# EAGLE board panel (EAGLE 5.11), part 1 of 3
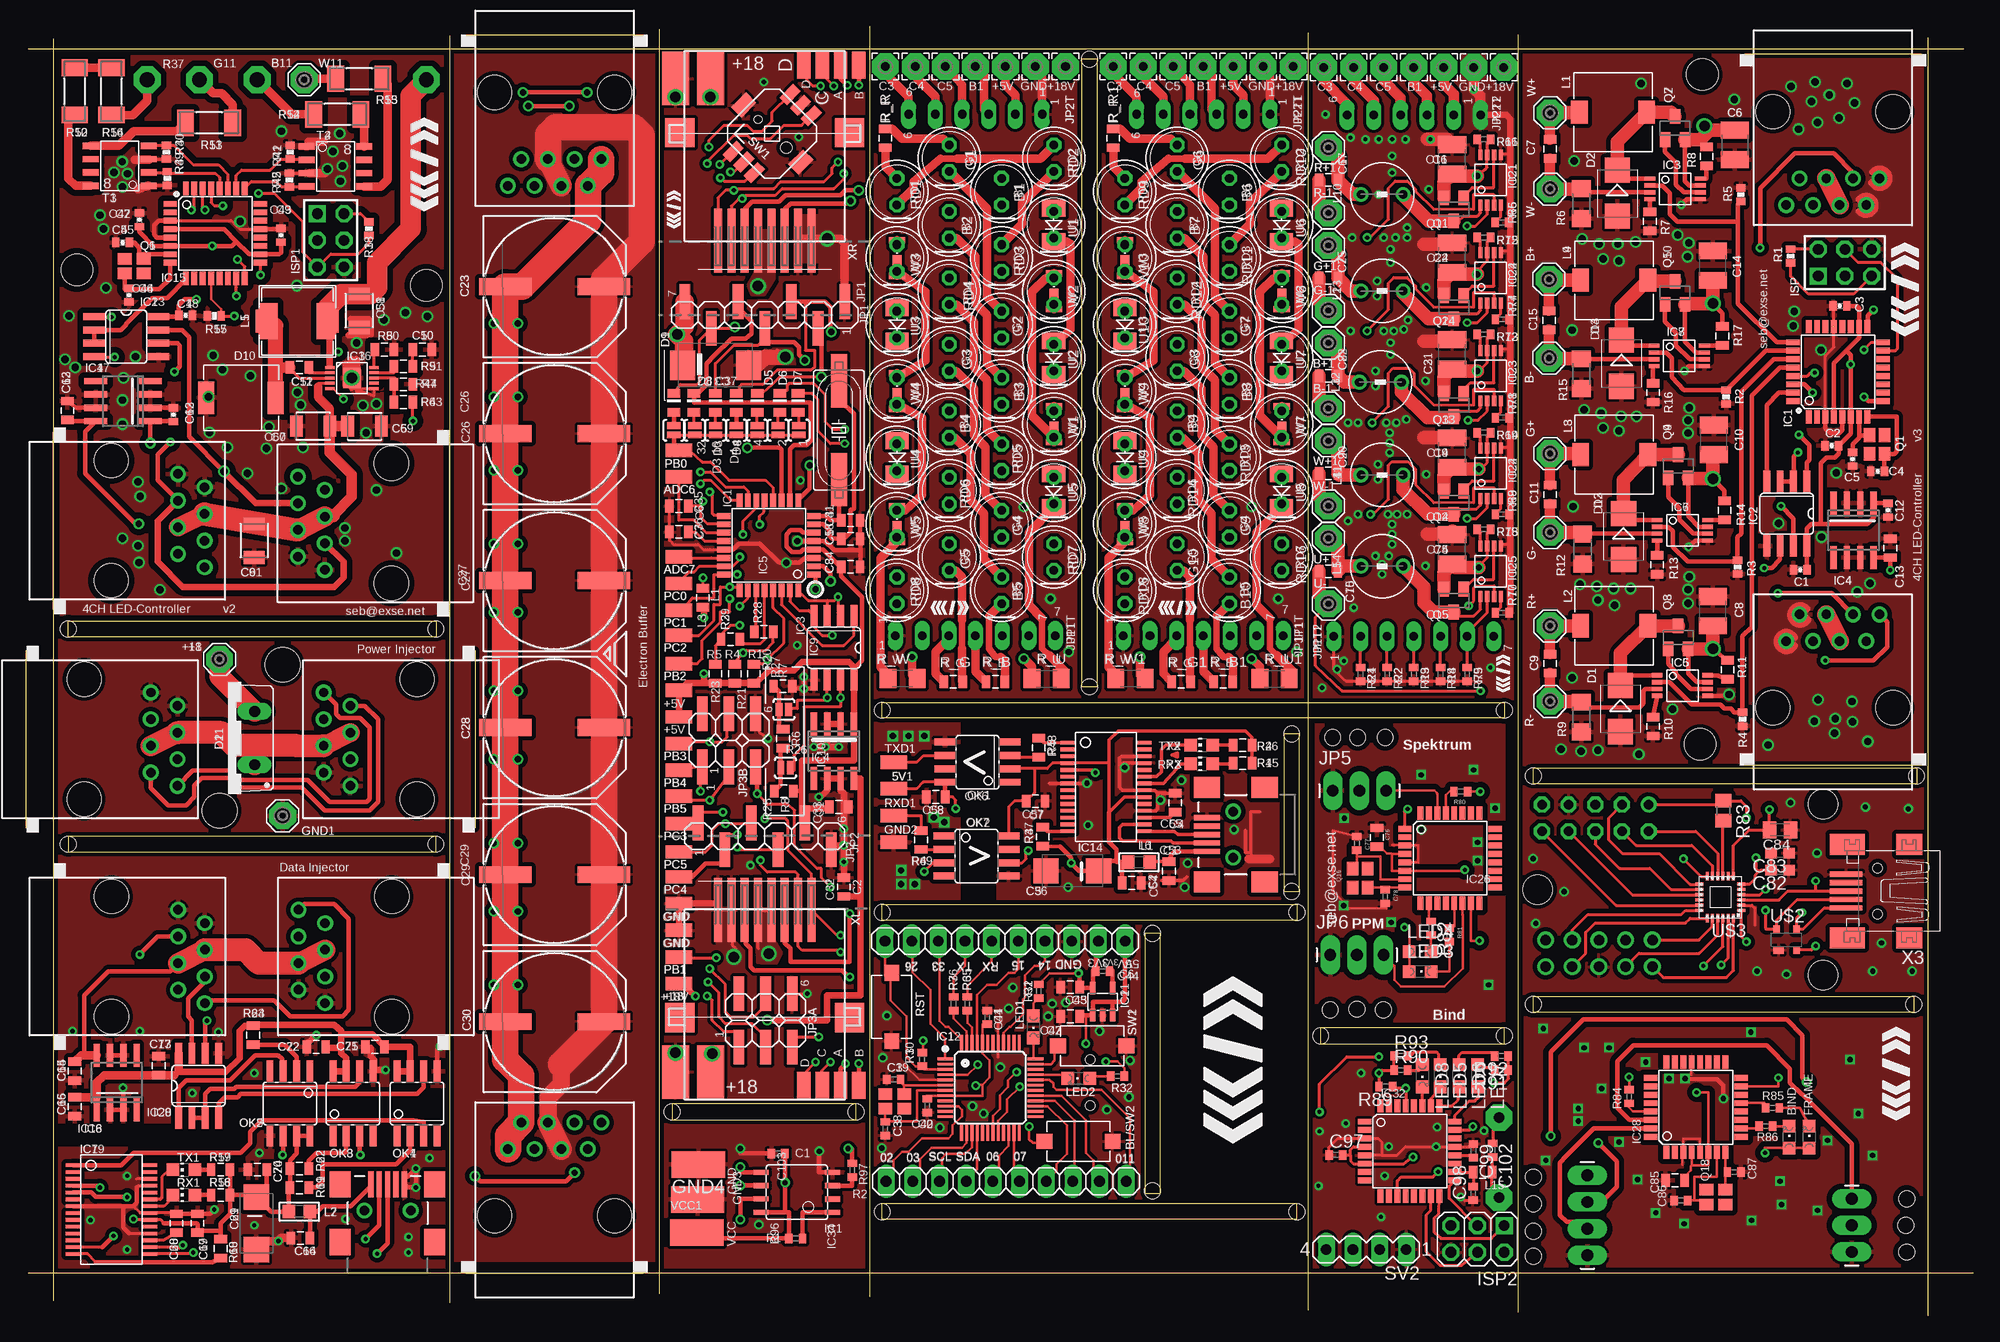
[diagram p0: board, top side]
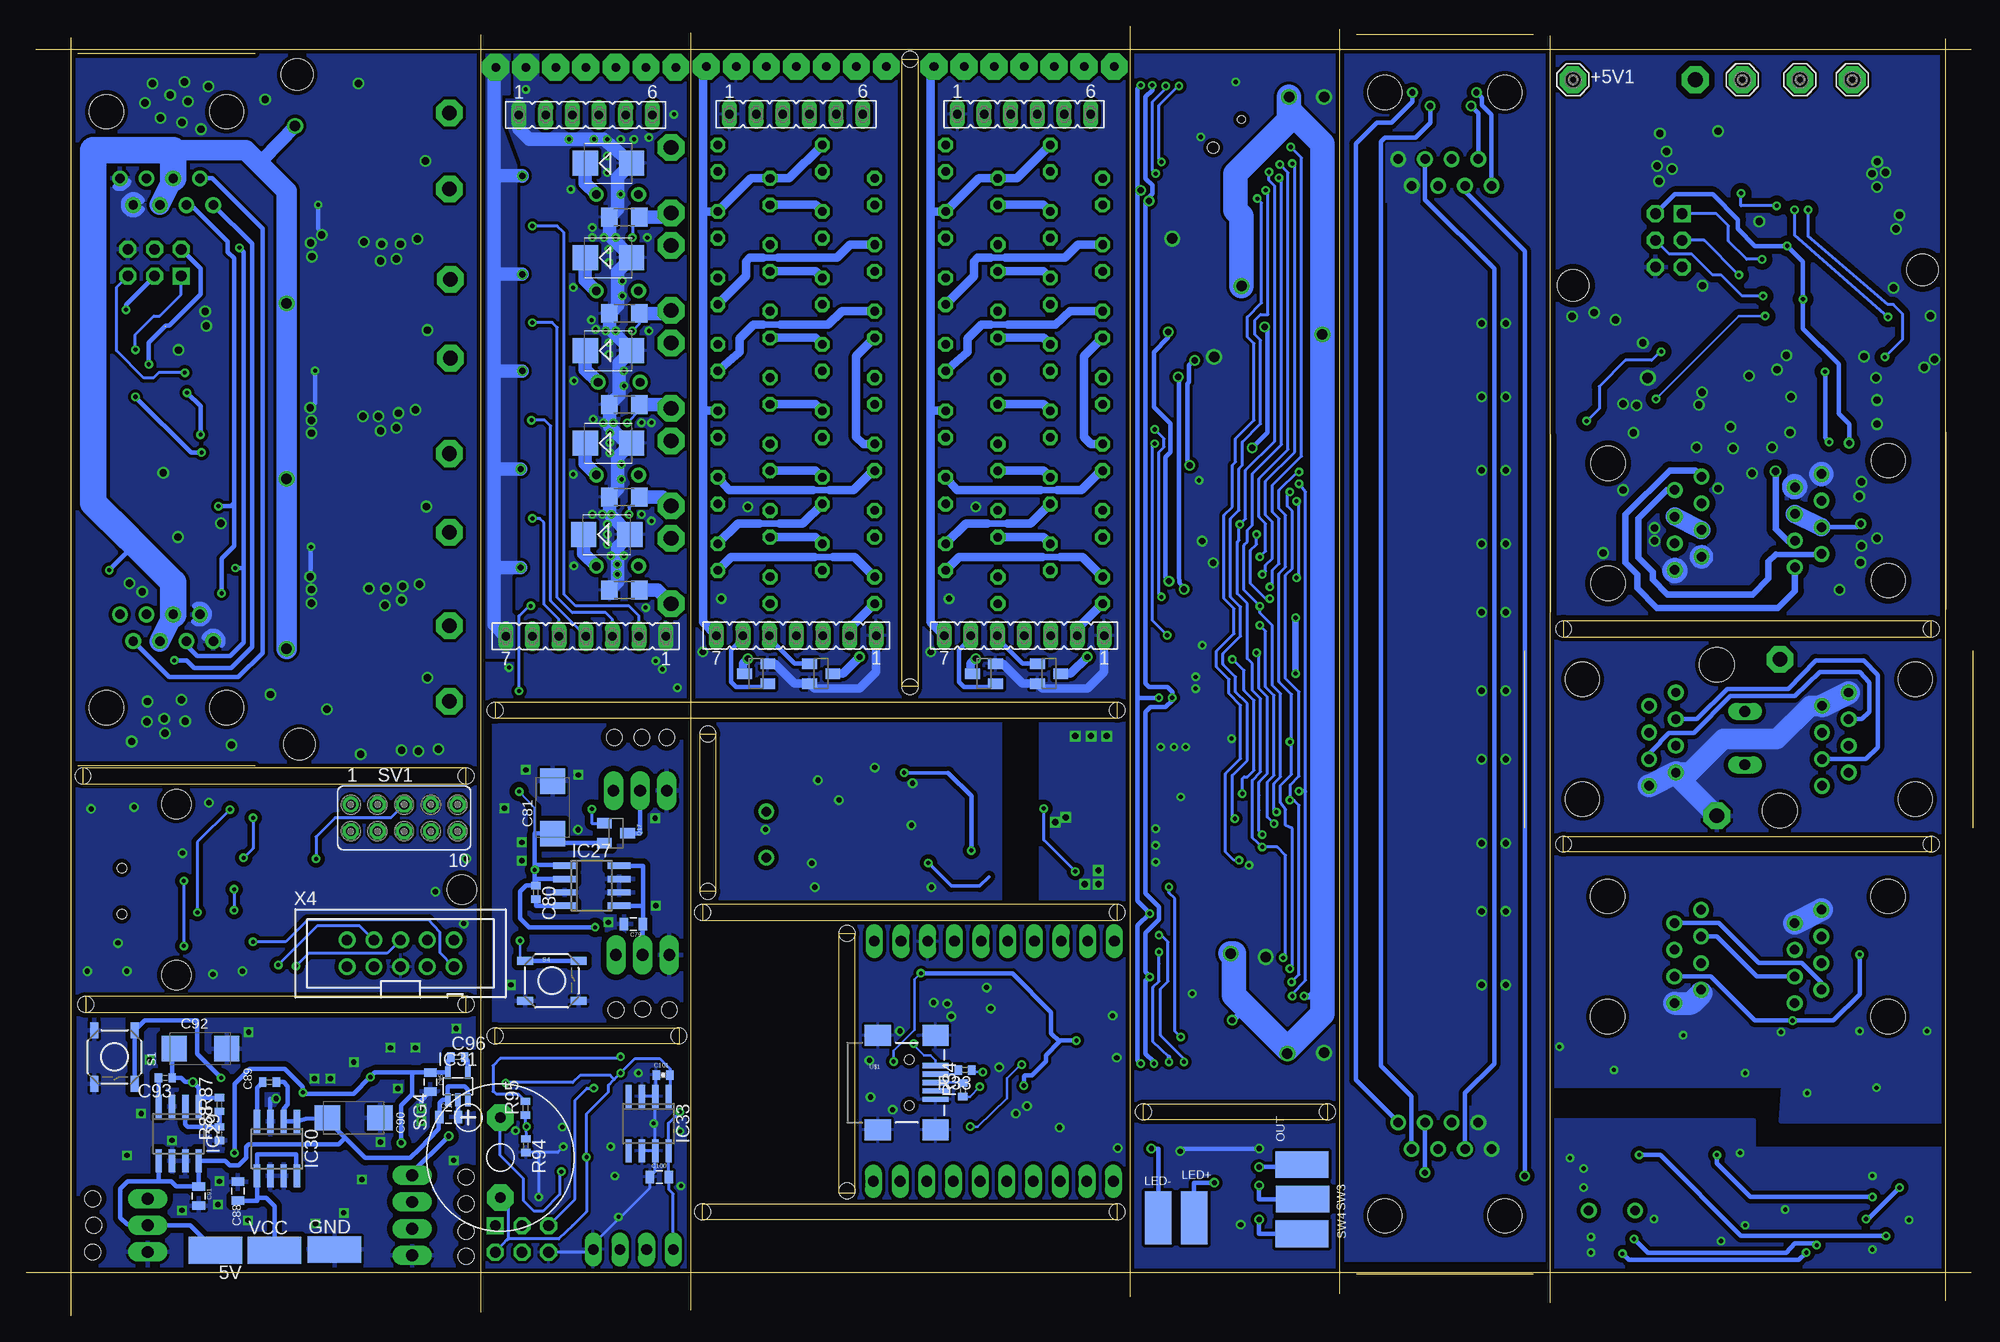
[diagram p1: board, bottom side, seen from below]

Size 185.41 x 122.8 mm. Coordinates in mm from the lower left corner, seen from the top.
Outline: 57 segments
Copper layers (1*16): Top 0.035mm / dielectric 1.5mm / Bottom 0.035mm
Design rules "default *": minimum track width 0.2mm, minimum drill 0.4mm, track to track 0.2mm, track to pad 0.2mm, pad to pad 0.2mm, via to via 0.2mm, smd to smd 0mil, copper to edge 0.4mm, drill to drill 8mil, minimum pad ring 0.3mm, minimum via ring 8mil, stop-mask expansion 4mil, vias tented up to drill 40mil, thermal gap 10mil
Holes 3.3 mm at 18.41,48.1 24.41,62
Holes 3 mm at 38.11,98.1 4.81,99.6 159.41,54.4 159.61,118.2
Holes 1.5 mm at 124.17,29.12 126.72,29.2 129.25,29.12 124.41,55.07 126.79,55.07 129.41,55.07 179.07,6.06 179,8.6 179.07,11.14 143.51,5.66 143.51,8.04 143.51,10.66 143.51,13.2 4.01,65.4 39.01,65.4 4.01,44.9 39.01,44.9 61.51,19.4 79.01,19.4 81.51,9.9 121.01,9.9 81.51,38.4 121.01,38.4 120.51,40.4 120.51,55.4 143.51,51.4 180.01,51.4 107.26,11.9 107.26,36.4 81.51,57.65 140.76,57.65 101.26,59.9 101.26,119.65 123.26,26.65 140.76,26.65 143.51,29.65 179.76,29.65
Holes 2.8 mm at 171.13,48.72 171.13,32.45 143.93,40.59
tRestrict: 2 lines

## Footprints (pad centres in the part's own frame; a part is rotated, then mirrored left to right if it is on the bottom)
SMD2,54-5,08 = smd 2.54 x 5.08: 1 0,0
SMD1,27-2,54 = smd 1.27 x 2.54: 1 0,0
SE14 = drill 1.397 pad 2.54 octagon: MP 0,0
LED5MM = drill 0.813 octagon: A -1.27,0; K 1.27,0
CHIPLED_0805 = smd 1.2 x 1.2: A 0,-1.05; C 0,1.05
SWITCH_MCTAEF = smd 1.5 x 1.4: 1 -3.25,0; 2 3.25,0
0402-CAP = smd 0.7 x 0.9: 1 -0.65,0; 2 0.65,0
C1210 = smd 1.6 x 2.7: 1 -1.4,0; 2 1.4,0
0805 = smd 0.8 x 1.2: 1 -0.9,0; 2 0.9,0
PANASONIC_H13 = smd 5 x 1.6: + 4.7,0; - -4.7,0
SMC_D = smd 2.4 x 2.8: + -3.15,0; - 3.15,0
C0402 = smd 0.7 x 0.9: 1 -0.65,0; 2 0.65,0
1210 = smd 1.2 x 2: 1 -1.6,0; 2 1.6,0
SMC_C = smd 2.4 x 2.4: + -2.5,0; - 2.5,0
C0603 = smd 1.1 x 1: 1 -0.85,0; 2 0.85,0
C0805K = smd 1.3 x 1.6: 1 -1,0; 2 1,0
SMB = smd 2.4 x 2.4: A 2.2,0; C -2.2,0
DIODE_0805 = smd 0.8 x 1.2: 1 -0.9,0; 2 0.9,0
DO214AB = smd 1.52 x 3.07: A 3.305,0; K -3.305,0
TO220ACS = drill 1.016 long: A 2.54,-2.54; C -2.54,-2.54
TQFP32-08 = smd 1.27 x 0.559: 1 -4.293,2.8; 2 -4.293,2; 3 -4.293,1.2; 4 -4.293,0.4; 5 -4.293,-0.4; 6 -4.293,-1.2; 7 -4.293,-2; 8 -4.293,-2.8; 17 4.293,-2.8; 18 4.293,-2; 19 4.293,-1.2; 20 4.293,-0.4; 21 4.293,0.4; 22 4.293,1.2; 23 4.293,2; 24 4.293,2.8 | smd 0.559 x 1.27: 9 -2.8,-4.293; 10 -2,-4.293; 11 -1.2,-4.293; 12 -0.4,-4.293; 13 0.4,-4.293; 14 1.2,-4.293; 15 2,-4.293; 16 2.8,-4.293; 25 2.8,4.293; 26 2,4.293; 27 1.2,4.293; 28 0.4,4.293; 29 -0.4,4.293; 30 -1.2,4.293; 31 -2,4.293; 32 -2.8,4.293
SO08 = smd 0.66 x 2.032: 1 -1.905,-3.073; 2 -0.635,-3.073; 3 0.635,-3.073; 4 1.905,-3.073; 5 1.905,3.073; 6 0.635,3.073; 7 -0.635,3.073; 8 -1.905,3.073
MSOP8 = smd 0.41 x 1.02: 1 -0.975,-2.4; 2 -0.325,-2.4; 3 0.325,-2.4; 4 0.975,-2.4; 5 0.975,2.4; 6 0.325,2.4; 7 -0.325,2.4; 8 -0.975,2.4
SO08' = smd 0.6 x 2.2: 1 -1.905,-2.6; 2 -0.635,-2.6; 3 0.635,-2.6; 4 1.905,-2.6; 5 1.905,2.6; 6 0.635,2.6; 7 -0.635,2.6; 8 -1.905,2.6
SOT23-5L = smd 0.55 x 1.2: 1 -0.95,-1.3; 2 0,-1.3; 3 0.95,-1.3; 4 0.95,1.3; 5 -0.95,1.3
LQFP48 = smd 1.5 x 0.25: 1 -4.3,2.75; 2 -4.3,2.25; 3 -4.3,1.75; 4 -4.3,1.25; 5 -4.3,0.75; 6 -4.3,0.25; 7 -4.3,-0.25; 8 -4.3,-0.75; 9 -4.3,-1.25; 10 -4.3,-1.75; 11 -4.3,-2.25; 12 -4.3,-2.75; 25 4.3,-2.75; 26 4.3,-2.25; 27 4.3,-1.75; 28 4.3,-1.25; 29 4.3,-0.75; 30 4.3,-0.25; 31 4.3,0.25; 32 4.3,0.75; 33 4.3,1.25; 34 4.3,1.75; 35 4.3,2.25; 36 4.3,2.75 | smd 0.25 x 1.5: 13 -2.75,-4.3; 14 -2.25,-4.3; 15 -1.75,-4.3; 16 -1.25,-4.3; 17 -0.75,-4.3; 18 -0.25,-4.3; 19 0.25,-4.3; 20 0.75,-4.3; 21 1.25,-4.3; 22 1.75,-4.3; 23 2.25,-4.3; 24 2.75,-4.3; 37 2.75,4.3; 38 2.25,4.3; 39 1.75,4.3; 40 1.25,4.3; 41 0.75,4.3; 42 0.25,4.3; 43 -0.25,4.3; 44 -0.75,4.3; 45 -1.25,4.3; 46 -1.75,4.3; 47 -2.25,4.3; 48 -2.75,4.3
SSOP28DB = smd 0.348 x 1.397: 1 -4.225,-3.656; 2 -3.575,-3.656; 3 -2.925,-3.656; 4 -2.275,-3.656; 5 -1.625,-3.656; 6 -0.975,-3.656; 7 -0.325,-3.656; 8 0.325,-3.656; 9 0.975,-3.656; 10 1.625,-3.656; 11 2.275,-3.656; 12 2.925,-3.656; 13 3.575,-3.656; 14 4.225,-3.656; 15 4.225,3.656; 16 3.575,3.656; 17 2.925,3.656; 18 2.275,3.656; 19 1.625,3.656; 20 0.975,3.656; 21 0.325,3.656; 22 -0.325,3.656; 23 -0.975,3.656; 24 -1.625,3.656; 25 -2.275,3.656; 26 -2.925,3.656; 27 -3.575,3.656; 28 -4.225,3.656
MSOP10-PAD = smd 0.305 x 0.889: 1 -1,-2.095; 2 -0.5,-2.095; 3 0,-2.095; 4 0.5,-2.095; 5 1,-2.095; 6 1,2.095; 7 0.5,2.095; 8 0,2.095; 9 -0.5,2.095; 10 -1,2.095 | smd 1.88 x 1.68: PAD 0,0
SOIC8 = smd 0.6 x 2.2: 1 -1.905,-2.6; 2 -0.635,-2.6; 3 0.635,-2.6; 4 1.905,-2.6; 5 1.905,2.6; 6 0.635,2.6; 7 -0.635,2.6; 8 -1.905,2.6
8S2 = smd 0.5 x 1.4: 1 -1.905,-3.404; 2 -0.645,-3.404; 3 0.625,-3.404; 4 1.895,-3.404; 5 1.905,3.404; 6 0.635,3.404; 7 -0.635,3.404; 8 -1.905,3.404
AVR-ISP-6 = drill 1.016 square: 1 -2.54,-1.27 | drill 1.016 octagon: 2 -2.54,1.27; 3 0,-1.27; 4 0,1.27; 5 2.54,-1.27; 6 2.54,1.27
2X03 = drill 1.016 square: 1 -2.54,-1.27 | drill 1.016 octagon: 2 -2.54,1.27; 3 0,-1.27; 4 0,1.27; 5 2.54,-1.27; 6 2.54,1.27
1X07SMD-REVERSE = smd 1.016 x 3.302: 1 -1.27,-1.27; 2 1.27,1.27; 3 3.81,-1.27; 4 6.35,1.27; 5 8.89,-1.27; 6 11.43,1.27; 7 13.97,-1.27
FE07 = drill 0.813 long: 1 -7.62,0; 2 -5.08,0; 3 -2.54,0; 4 0,0; 5 2.54,0; 6 5.08,0; 7 7.62,0
1X06SMD = smd 1.016 x 3.302: 1 -1.27,1.27; 2 1.27,-1.27; 3 3.81,1.27; 4 6.35,-1.27; 5 8.89,1.27; 6 11.43,-1.27
FE06 = drill 0.813 long: 1 -6.35,0; 2 -3.81,0; 3 -1.27,0; 4 1.27,0; 5 3.81,0; 6 6.35,0
1X10 = drill 1.016 long: 1 -11.43,0; 2 -8.89,0; 3 -6.35,0; 4 -3.81,0; 5 -1.27,0; 6 1.27,0; 7 3.81,0; 8 6.35,0; 9 8.89,0; 10 11.43,0
2X03SMD = smd 1.016 x 3.302: 1 -1.27,-3.81; 2 -1.27,1.27; 3 1.27,-3.81; 4 1.27,1.27; 5 3.81,-3.81; 6 3.81,1.27
1X03_LONGPADS = drill 1.118 pad 1.88 long: 1 0,0; 2 2.54,0; 3 5.08,0
PIS2816 = smd 2.2 x 1.6: P$1 0,3.2; P$2 0,-3.2
IHLP-2525CZ = smd 1.83 x 3.43: P$1 -2.77,0; P$2 2.77,0
X22 = smd 1.3 x 1.1: 1 0.9,0.7; 2 -0.9,0.7; 3 -0.9,-0.7; 4 0.9,-0.7
RLF7030 = smd 2 x 2.2: P$1 -2.95,0; P$2 2.95,0
L0805 = smd 1.2 x 1.3: 1 -1.016,0; 2 1.016,0
WE-TI_S/M = drill 0.813 round: 1 -2,0; 2 2,0
SOIC08 = smd 0.66 x 2.032: 1 -1.905,-3.073; 2 -0.635,-3.073; 3 0.635,-3.073; 4 1.905,-3.073; 5 1.905,3.073; 6 0.635,3.073; 7 -0.635,3.073; 8 -1.905,3.073
2,54/0,8 = drill 0.813 pad 2.54 octagon: 1 0,0
SOT23 = smd 1 x 1.4: 1 -0.95,-1.1; 2 0.95,-1.1; 3 0,1.1
0402-RES = smd 0.7 x 0.9: 1 -0.65,0; 2 0.65,0
R1206 = smd 1.6 x 1.803: 1 -1.422,0; 2 1.422,0
R0402 = smd 0.7 x 0.9: 1 -0.65,0; 2 0.65,0
MINI_MELF-0207R = smd 1.6 x 2.5: 1 -2.25,0; 2 2.25,0
R0805 = smd 1.3 x 1.5: 1 -0.95,0; 2 0.95,0
1206 = smd 1.6 x 1.8: 1 -1.4,0; 2 1.4,0
CHIP-LED0805 = smd 1.2 x 1.2: A 0,-1.05; C 0,1.05
TACTILE_SWITCH_SMD = smd 1.524 x 0.762: 1 -2.54,1.905; 2 2.54,1.905; 3 -2.54,-1.905; 4 2.54,-1.905
F/CM12P = drill 1.016 pad 2.54 octagon: + 3.81,0; - -3.81,0
SJ_2S-NO = smd 0.635 x 1.27: 1 -0.45,0; 2 0.45,0
1X04_LONGPADS = drill 1.118 pad 1.88 long: 1 0,0; 2 2.54,0; 3 5.08,0; 4 7.62,0
FE05-2 = drill 0.914 round: 1 -5.08,1.27 | drill 0.914 octagon: 2 -5.08,-1.27; 3 -2.54,1.27; 4 -2.54,-1.27; 5 0,1.27; 6 0,-1.27; 7 2.54,1.27; 8 2.54,-1.27; 9 5.08,1.27; 10 5.08,-1.27
MA04-1 = drill 1.016 long: 1 -3.81,0; 2 -1.27,0; 3 1.27,0; 4 3.81,0
MCMT5-F-V_ADAPTED = smd 1.858 x 1: 1 -3.829,1.425; 2 -3.829,0; 3 -3.829,-1.425; 4 3.829,1.425; 5 3.829,0; 6 3.829,-1.425 | smd 2 x 1.394: TAB1 0,3.847; TAB2 0,-3.847 | hole 1.05: 0,-1.9 | hole 0.75: 0,1.9
SO-8 = smd 1.524 x 0.61: 1 -2.743,1.27; 2 -2.743,0; 3 -2.743,-1.27; 4 -2.743,-2.54; 5 2.743,-2.54; 6 2.743,-1.27; 7 2.743,0; 8 2.743,1.27
PLCC2 = smd 1.6 x 2.2: P$1 -1.6,0; P$2 1.6,0
USB-MINIB = smd 2.5 x 0.5: D+ 2.5,0; D- 2.5,0.8; GND 2.5,-1.6; ID 2.5,-0.8; VBUS 2.5,1.6 | smd 2.5 x 2: MTN1 -3,4.5; MTN2 2.5,4.5; MTN3 -3,-4.5; MTN4 2.5,-4.5 | hole 0.9: 0,2.2; 0,-2.2
SOT143-R = smd 1 x 0.7: 1 -0.75,-1 | smd 0.6 x 0.7: 2 0.95,-1; 3 0.95,1; 4 -0.95,1
S-PQFP-N24(RGE) = smd 0.8 x 0.3: 1 -2.5,1.75; 2 -2.5,1.25; 3 -2.5,0.75; 4 -2.5,0.25; 5 -2.5,-0.25; 6 -2.5,-0.75; 13 1.5,-0.75; 14 1.5,-0.25; 15 1.5,0.25; 16 1.5,0.75; 17 1.5,1.25; 18 1.5,1.75 | smd 0.3 x 0.8: 7 -1.75,-1.5; 8 -1.25,-1.5; 9 -0.75,-1.5; 10 -0.25,-1.5; 11 0.25,-1.5; 12 0.75,-1.5; 19 0.75,2.5; 20 0.25,2.5; 21 -0.25,2.5; 22 -0.75,2.5; 23 -1.25,2.5; 24 -1.75,2.5
NICHIA_NSSL157T-H3 = smd 0.64 x 0.86: A@1 1.08,0 | smd 0.6 x 1.55: A@2 1.7,0; K@1 -1.7,0 | smd 1.66 x 0.86: K@2 -0.57,0
RJ45-NO-SHIELD = drill 0.9 pad 1.4 round: 1 -4.445,6.35; 2 -3.175,8.89; 3 -1.905,6.35; 4 -0.635,8.89; 5 0.635,6.35; 6 1.905,8.89; 7 3.175,6.35; 8 4.445,8.89 | hole 3.251: -5.715,0; 5.715,0
32005-301 = smd 3.1 x 0.5: 1 3,1.6; 2 3,0.8; 3 3,0; 4 3,-0.8; 5 3,-1.6 | smd 2.5 x 2: M1 -3,-4.45; M2 -3,4.45 | smd 3.3 x 2: M3 2.9,4.45; M4 2.9,-4.45 | hole 0.9: 0,2.2; 0,-2.2
PAK100/2500-10 = drill 1 pad 1.422 round: 1 -5.08,-1.27; 2 -5.08,1.27; 3 -2.54,-1.27; 4 -2.54,1.27; 5 0,-1.27; 6 0,1.27; 7 2.54,-1.27; 8 2.54,1.27; 9 5.08,-1.27; 10 5.08,1.27
HC49UP-SMALL = smd 5.08 x 1.524: 1 -4.699,0; 2 4.699,0
USB-MINIB-NOSTOP = smd 2.5 x 0.5: D+ 2.5,0; D- 2.5,0.8; GND 2.5,-1.6; ID 2.5,-0.8; VBUS 2.5,1.6 | smd 2.5 x 2: G1 -3,-4.5; G2 -3,4.5; G3 2.5,4.5; G4 2.5,-4.5 | drill 0.9 pad 0.8 round: H1 0,2.2 | drill 0.9 pad 0.787 round: H2 0,-2.2
85502-5008-SMALL = smd 6.096 x 0.762: 1 10.211,4.445; 2 10.211,3.175; 3 10.211,1.905; 4 10.211,0.635; 5 10.211,-0.635; 6 10.211,-1.905; 7 10.211,-3.175; 8 10.211,-4.445 | smd 2.794 x 2.794: P$1 -0.076,-8.077; P$2 -0.076,8.077

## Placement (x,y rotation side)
5V  [SMD2,54-5,08]  167.41,6.21 90 bottom
5V1  [SMD1,27-2,54]  82.61,50.17 270 top
+1  SE14  [SE14]  18.41,62.5 0 top
+5V1  SE14  [SE14]  38.11,117.7 0 bottom
+18_L  [SMD2,54-5,08]  65.16,23.2 180 top
+18_R  [SMD2,54-5,08]  65.16,117.82 180 top
A_L  [SMD1,27-2,54]  77.54,21.93 180 top
A_R  [SMD1,27-2,54]  77.54,119.09 180 top
ADC6  WIREPADSMD1,27-254  [SMD1,27-2,54]  62.15,79.88 90 top
ADC7  WIREPADSMD1,27-254  [SMD1,27-2,54]  62.15,72.26 270 top
B1  [LED5MM]  92.88,107.06 270 top
B2  [LED5MM]  87.9,103.89 270 top
B3  [LED5MM]  92.88,88.07 270 top
B4  [LED5MM]  87.9,84.9 270 top
B5  [LED5MM]  92.88,69.08 270 top
B6  [LED5MM]  114.58,107.06 270 top
B7  [LED5MM]  109.6,103.89 270 top
B8  [LED5MM]  114.58,88.07 270 top
B9  [LED5MM]  109.6,84.9 270 top
B10  [LED5MM]  114.58,69.08 270 top
B11  SE14  [SE14]  21.98,117.7 0 bottom
B+  SE14  [SE14]  145.01,98.7 90 top
B+1  SE14  [SE14]  124.01,92.64 270 top
B-  SE14  [SE14]  145.01,91.2 90 top
B-1  SE14  [SE14]  124.01,86.41 270 top
B_L  [SMD1,27-2,54]  79.29,21.93 180 top
B_R  [SMD1,27-2,54]  79.29,119.09 180 top
BIND  [CHIPLED_0805]  167.88,17.01 0 top
BL/SW2  SWITCH_MCTAEF  [SWITCH_MCTAEF]  100.21,16.6 180 top
C  WIREPADSMD1,27-254  [SMD1,27-2,54]  75.8,119.09 180 top
C1  100nF  [0402-CAP]  168.94,71.05 180 top
C2  100nF  [0402-CAP]  171.95,82.86 180 top
C3  100nF  [0402-CAP]  172.72,96.15 180 top
C4  22pF  [0402-CAP]  176.3,80.42 0 top
C5  22pF  [0402-CAP]  173.92,81.56 90 top
C6  2.2µF / 50V  [C1210]  162.71,111.5 270 top
C7  1µF  [0805]  145.11,111.1 90 top
C8  2.2µF / 50V  [C1210]  160.61,67.1 90 top
C9  1µF  [0805]  145.11,62.1 90 top
C10  2.2µF / 50V  [C1210]  160.71,83.4 90 top
C11  1µF  [0805]  145.11,78.2 90 top
C12  100nF  [0402-CAP]  177.31,76.7 90 top
C13  1µF  [0805]  177.51,73.1 270 top
C14  2.2µF / 50V  [C1210]  160.61,100 90 top
C15  1µF  [0805]  145.01,94.8 90 top
C16  2.2µF / 50V  [C1210]  135.79,110.13 90 top
C17  1µF  [0805]  124.01,108.16 0 top
C18  22p  [0805]  78.5,75.75 180 top
C19  2.2µF / 50V  [C1210]  135.79,82.19 90 top
C20  1µF  [0805]  124.01,80.22 0 top
C21  2.2µF / 50V  [C1210]  135.79,91.56 90 top
C22  1µF  [0805]  124.01,89.51 0 top
C23  [PANASONIC_H13]  50.31,98 0 top
C24  2.2µF / 50V  [C1210]  135.79,100.77 90 top
C25  1µF  [0805]  124.01,98.83 0 top
C26  [PANASONIC_H13]  50.31,84 0 top
C27  [PANASONIC_H13]  50.31,70 0 top
C28  [PANASONIC_H13]  50.31,56 0 top
C29  [PANASONIC_H13]  50.31,42 0 top
C30  [PANASONIC_H13]  50.31,28 0 top
C31  22p  [0805]  78.5,74 180 top
C32  1u  [0805]  77.86,40.82 90 top
C33  100n  [0805]  77.39,48.44 0 top
C34  100n  [0805]  78.5,71.3 0 top
C35  100n  [0805]  62.15,77.1 0 top
C36  100n  [0805]  62.15,74.64 0 top
C37  [SMC_D]  65.64,90.51 0 top
C38  22pF  [C0402]  81.81,17.8 90 top
C39  22pF  [C0402]  82.61,22.5 0 top
C40  100nF  [C0402]  85.81,20 90 top
C41  100nF  [C0402]  91.51,28.4 270 top
C42  1µF  [0805]  99.41,28.5 180 top
C43  10µF  [0805]  99.41,31.3 180 top
C44  10nF  [C0402]  102.51,32.8 0 top
C45  22pF  [0402-CAP]  9.17,102.19 0 top
C46  22pF  [0402-CAP]  9.79,97.19 90 top
C47  100nF  [0402-CAP]  10.77,104.36 90 top
C48  100nF  [0402-CAP]  15.18,95.25 0 top
C49  100nF  [0402-CAP]  24.26,102.89 90 top
C50  680pF  [0805]  37.71,92 180 top
C51  47µF 16V  [1210]  31.71,95.7 270 top
C52  1µF  [0805]  26.01,90.3 0 top
C53  10nF  [0805]  108.82,42.34 270 top
C54  100nF  [0805]  105.26,41.21 0 top
C55  100nF  [0805]  109.4,48.84 90 top
C56  4.7µF  [SMC_C]  99.62,42.36 180 top
C57  100nF  [0805]  96.11,49 180 top
C58  100nF  [0805]  86.61,49.4 180 top
C59  4.7µF 50V  [1210]  32.21,84.7 0 top
C60  4.7µF 50V  [1210]  27.31,84.7 180 top
C61  4.7µF 50V  [1210]  21.71,73.8 270 top
C62  1µF  [0805]  3.91,86.2 270 top
C63  100nF  [0402-CAP]  14.01,85.8 270 top
C64  1uF  [0805]  4.61,23.3 90 top
C65  100nF  [0805]  4.61,19.9 90 top
C66  10nF  [0805]  26.11,7.4 180 top
C67  100nF  [0805]  16.31,8.8 90 top
C68  100nF  [0805]  14.31,8.8 90 top
C69  4.7µF  [SMC_C]  21.91,8.8 270 top
C70  100nF  [0805]  22.01,13.9 0 top
C71  100nF  [0805]  33.21,25.6 180 top
C72  100nF  [0805]  27.61,25.6 180 top
C73  100nF  [0805]  12.61,23.8 90 top
C74  2.2µF / 50V  [C1210]  135.79,72.98 90 top
C75  1µF  [0805]  124.01,70.89 0 top
C76  100n  [0805]  128.62,45.55 90 top
C77  22n  [C0402]  126.72,44.99 270 top
C78  22n  [C0402]  129.41,39.91 90 top
C79  1µF  [0805]  127.59,37.29 180 bottom
C80  10nF  [C0402]  136.87,40.31 270 bottom
C81  [SMC_C]  135.29,48.41 90 bottom
C82  [C0603]  167.01,42.44 180 top
C83  [C0603]  167.01,44.06 180 top
C84  [C0805K]  167,46.27 180 top
C85  100n  [0805]  157.01,12.88 180 top
C86  22p  [C0402]  157.56,10.98 0 top
C87  22p  [C0402]  162.64,13.67 180 top
C88  1µF  [0805]  165.26,11.85 90 bottom
C89  10nF  [C0402]  162.25,22.25 180 bottom
C90  10µF  [SMC_C]  154.23,18.83 0 bottom
C91  1µF  [0805]  168.99,11.37 270 bottom
C92  10µF  [SMC_C]  168.84,25.42 0 bottom
C93  10nF  [C0402]  172.17,22.64 180 bottom
C94  1µF  [0805]  145.18,18.91 0 bottom
C95  10µF  [0805]  146.93,22.25 270 bottom
C96  10nF  [C0402]  144.31,24.63 0 bottom
C97  [C0402]  124.71,15.31 0 top
C98  [C0402]  137.78,11.65 90 top
C99  [C0402]  137.81,15.7 270 top
C100  1µF  [0805]  125.12,13.21 0 bottom
C101  100nF  [0402-CAP]  124.76,22.91 0 bottom
C102  [C0402]  139.62,15.76 270 top
C103  [C0402]  71.6,15.45 0 top
C_L  WIREPADSMD1,27-254  [SMD1,27-2,54]  75.8,21.93 180 top
D  WIREPADSMD1,27-254  [SMD1,27-2,54]  74.05,119.09 180 top
D1  MBRS140  [SMB]  151.81,57.8 270 top
D2  MBRS140  [SMB]  151.51,106.9 270 top
D3  [DIODE_0805]  65.64,86.94 270 top
D4  [DIODE_0805]  67.62,86.94 270 top
D5  [DIODE_0805]  69.61,86.94 270 top
D6  [DIODE_0805]  71.75,86.94 270 top
D7  [DIODE_0805]  73.5,86.94 270 top
D8  [DIODE_0805]  63.57,86.94 270 top
D9  [DIODE_0805]  61.67,86.94 270 top
D10  MBRS340  [DO214AB]  20.46,87.41 180 top
D11  [TO220ACS]  19.21,55 90 top
D12  MBRS140  [SMB]  152.11,74.2 270 top
D13  MBRS140  [SMB]  151.91,90.7 270 top
D14  MBRS140  [SMB]  129.98,109.76 0 bottom
D15  MBRS140  [SMB]  129.98,83.09 0 bottom
D16  MBRS140  [SMB]  129.98,91.91 0 bottom
D17  MBRS140  [SMB]  129.98,100.75 0 bottom
D18  MBRS140  [SMB]  130.14,74.39 0 bottom
D_L  WIREPADSMD1,27-254  [SMD1,27-2,54]  74.05,21.93 0 top
FRAME  [CHIPLED_0805]  169.79,17.01 0 top
G1  [LED5MM]  87.9,110.22 270 top
G2  [LED5MM]  92.88,94.4 270 top
G3  [LED5MM]  87.9,91.23 270 top
G4  [LED5MM]  92.88,75.41 270 top
G5  [LED5MM]  87.9,72.24 270 top
G6  [LED5MM]  109.6,110.22 270 top
G7  [LED5MM]  114.58,94.4 270 top
G8  [LED5MM]  109.6,91.23 270 top
G9  [LED5MM]  114.58,75.41 270 top
G10  [LED5MM]  109.6,72.24 270 top
G11  SE14  [SE14]  16.5,117.7 0 bottom
G+  SE14  [SE14]  145.11,82.1 90 top
G+1  SE14  [SE14]  124.01,101.93 270 top
G-  SE14  [SE14]  145.11,74.6 90 top
G-1  SE14  [SE14]  124.01,95.74 270 top
GND  [SMD2,54-5,08]  156.06,6.29 270 bottom
GND1  SE14  [SE14]  24.41,47.6 0 top
GND2  [SMD1,27-2,54]  82.61,45.09 270 top
GND3  [SMD2,54-5,08]  63.93,11.06 270 top
GND4  [SMD2,54-5,08]  64.01,14.4 90 top
GND_L  [SMD2,54-5,08]  61.83,23.2 180 top
GND_R  [SMD2,54-5,08]  61.83,117.82 180 top
IC1  MEGA48/88/168-AU  [TQFP32-08]  172.54,89.9 90 top
IC2  MAX487CSA  [SO08]  167.65,76.38 180 top
IC3  LM3401  [MSOP8]  157.01,107.3 270 top
IC4  78L05SMD  [SO08']  174.01,74.8 180 top
IC5  MEGA8-AI  [TQFP32-08]  70.72,73.37 180 top
IC6  LM3401  [MSOP8]  157.71,60 270 top
IC7  LM3401  [MSOP8]  157.71,74.8 270 top
IC8  LM3401  [MSOP8]  157.41,91.4 270 top
IC9  MAX487  [SO08]  76.91,63.6 180 top
IC10  78L05  [SO08']  76.91,53.76 180 top
IC11  LT1761  [SOT23-5L]  102.51,29.9 0 top
IC12  [LQFP48]  91.81,21.7 0 top
IC13  MAX487CSA  [SO08]  9.53,93.24 270 top
IC14  FT232RL  [SSOP28DB]  102.82,50.35 270 top
IC15  MEGA48/88/168-AU  [TQFP32-08]  18.01,103.07 0 top
IC16  LT3972  [MSOP10-PAD]  31.01,89.3 270 top
IC17  78L05SMD  [SO08']  9.21,87.1 90 top
IC18  78L05  [SO08']  8.61,22.2 0 top
IC19  FT232RL  [SSOP28DB]  8.11,10.1 270 top
IC20  MAX487  [SO08]  16.41,21.9 0 top
IC21  LM3401  [MSOP8]  139.45,108.16 0 top
IC22  LM3401  [MSOP8]  139.45,80.22 0 top
IC23  LM3401  [MSOP8]  139.45,89.51 0 top
IC24  LM3401  [MSOP8]  139.45,98.83 0 top
IC25  LM3401  [MSOP8]  139.45,70.89 0 top
IC26  atmega88  [TQFP32-08]  135.58,43.56 0 top
IC27  LT1763CS8-3.3  [SOIC8]  131.56,40.94 270 bottom
IC28  atmega88  [TQFP32-08]  158.99,19.84 90 top
IC29  LT1763CS8-ADJ  [SOIC8]  170.9,17.33 180 bottom
IC30  LT1763CS8-5  [SOIC8]  161.53,15.9 180 bottom
IC31  LT1761  [SOT23-5L]  144.31,21.85 0 bottom
IC32  MEGA48/88/168-AU  [TQFP32-08]  131.76,15.68 0 top
IC33  78L05SMD  [SO08']  126.15,18.29 180 bottom
IC34  TINY13V-10SU  [8S2]  73.37,11.75 90 top
ISP  AVR-ISP-6  [AVR-ISP-6]  173.2,100.28 0 top
ISP1  AVR-ISP-6  [AVR-ISP-6]  28.99,102.42 270 top
ISP2  ISP  [2X03]  138.21,7.3 180 top
JP1  [1X07SMD-REVERSE]  76.68,95.31 180 top
JP1T  [FE07]  90.39,64.77 180 bottom
JP1T1  [FE07]  112.09,64.77 180 bottom
JP1T2  [FE07]  132.14,64.7 180 bottom
JP2  [1X06SMD]  75.41,45.65 180 top
JP2T  [FE06]  90.39,114.42 0 bottom
JP2T1  [FE06]  112.09,114.42 0 bottom
JP2T2  [FE06]  132.14,114.35 0 bottom
JP3  [1X10]  93.31,12.79 180 top
JP3A  ISP_A  [2X03SMD]  69.13,29.39 0 top
JP3B  ISP_B  [2X03SMD]  65.64,56.06 0 top
JP4  [1X10]  93.21,35.65 0 top
JP5  [1X03_LONGPADS]  124.41,49.99 0 top
JP6  [1X03_LONGPADS]  124.17,34.36 0 top
L1  33µH / 1A  [PIS2816]  151.11,114.6 270 top
L1A1  8.2µH  [IHLP-2525CZ]  25.81,94.7 180 top
L2  33µH / 1A  [PIS2816]  151.21,65.7 270 top
L3  10uH  [0805]  64.45,68.37 90 top
L4  [X22]  82.7,20.41 180 top
L5  3,3µH  [RLF7030]  25.81,94.7 180 top
L6  BEAD  [L0805]  105.96,43.17 180 top
L7  BEAD  [L0805]  26.01,9.9 180 top
L8  33µH / 1A  [PIS2816]  151.21,82 270 top
L9  33µH / 1A  [PIS2816]  151.21,98.6 270 top
L10  33µH / 1A  [WE-TI_S/M]  129.11,106.78 0 top
L11  33µH / 1A  [WE-TI_S/M]  129.11,80.06 0 top
L12  33µH / 1A  [WE-TI_S/M]  128.96,88.9 0 top
L13  33µH / 1A  [WE-TI_S/M]  129.11,97.59 0 top
L14  33µH / 1A  [WE-TI_S/M]  129.11,71.38 0 top
L15  L0805  [0805]  138.69,13.67 180 top
LED1  [CHIPLED_0805]  95.91,27.5 180 top
LED2  [CHIPLED_0805]  100.21,22.6 90 top
LED3  [CHIPLED_0805]  132.75,32.77 270 top
LED4  [CHIPLED_0805]  132.75,34.67 270 top
LED5  [CHIPLED_0805]  134.66,22.84 180 top
LED6  [CHIPLED_0805]  136.44,22.84 180 top
LED7  [CHIPLED_0805]  138.22,22.84 180 top
LED8  [CHIPLED_0805]  132.95,22.84 180 top
LED+  [SMD2,54-5,08]  74.19,9.32 0 bottom
LED-  [SMD2,54-5,08]  77.61,9.32 0 bottom
OK4  HCPL0601  [SOIC08]  37.21,20.2 0 top
OK5  HCPL0601  [SOIC08]  25.11,20.2 180 top
OK6  HCPL0601  [SOIC08]  90.59,52.71 90 top
OK7  HCPL0601  [SOIC08]  90.49,43.77 270 top
OK8  HCPL0601  [SOIC08]  31.11,20.2 0 top
OUT  [SMD2,54-5,08]  63.93,14.38 270 bottom
P+5T  WIREPAD2,54/0,8  [2,54/0,8]  93.25,118.96 270 top
P+5T1  WIREPAD2,54/0,8  [2,54/0,8]  114.95,118.96 270 top
P+5T2  WIREPAD2,54/0,8  [2,54/0,8]  134.99,118.89 270 top
P+18T  WIREPAD2,54/0,8  [2,54/0,8]  98.96,118.96 270 top
P+18T1  WIREPAD2,54/0,8  [2,54/0,8]  120.66,118.96 270 top
P+18T2  WIREPAD2,54/0,8  [2,54/0,8]  140.71,118.89 270 top
PAD1  WIREPADSMD1,27-254  [SMD1,27-2,54]  62.15,36.7 90 top
PAD2  WIREPADSMD1,27-254  [SMD1,27-2,54]  62.15,31.62 90 top
PAD3  WIREPADSMD1,27-254  [SMD1,27-2,54]  62.15,59.56 90 top
PAD4  WIREPADSMD1,27-254  [SMD1,27-2,54]  62.15,57.02 90 top
PAD5  WIREPADSMD1,27-254  [SMD1,27-2,54]  62.15,39.24 90 top
PB0  WIREPADSMD1,27-254  [SMD1,27-2,54]  62.15,82.42 270 top
PB1  WIREPADSMD1,27-254  [SMD1,27-2,54]  62.15,34.16 270 top
PB1T  WIREPAD2,54/0,8  [2,54/0,8]  90.39,118.96 270 top
PB1T1  WIREPAD2,54/0,8  [2,54/0,8]  112.09,118.96 270 top
PB1T2  WIREPAD2,54/0,8  [2,54/0,8]  132.14,118.89 270 top
PB2  WIREPADSMD1,27-254  [SMD1,27-2,54]  62.15,62.1 270 top
PB3  WIREPADSMD1,27-254  [SMD1,27-2,54]  62.15,54.48 270 top
PB4  WIREPADSMD1,27-254  [SMD1,27-2,54]  62.15,51.94 270 top
PB5  WIREPADSMD1,27-254  [SMD1,27-2,54]  62.15,49.48 270 top
PC0  WIREPADSMD1,27-254  [SMD1,27-2,54]  62.15,69.72 90 top
PC1  WIREPADSMD1,27-254  [SMD1,27-2,54]  62.15,67.18 90 top
PC2  WIREPADSMD1,27-254  [SMD1,27-2,54]  62.15,64.79 90 top
PC3  WIREPADSMD1,27-254  [SMD1,27-2,54]  62.15,46.86 90 top
PC3T  WIREPAD2,54/0,8  [2,54/0,8]  81.82,118.96 270 top
PC3T1  WIREPAD2,54/0,8  [2,54/0,8]  103.52,118.96 270 top
PC3T2  WIREPAD2,54/0,8  [2,54/0,8]  123.56,118.89 270 top
PC4  WIREPADSMD1,27-254  [SMD1,27-2,54]  62.15,41.78 90 top
PC4T  WIREPAD2,54/0,8  [2,54/0,8]  84.68,118.96 270 top
PC4T1  WIREPAD2,54/0,8  [2,54/0,8]  106.38,118.96 270 top
PC4T2  WIREPAD2,54/0,8  [2,54/0,8]  126.42,118.89 270 top
PC5  WIREPADSMD1,27-254  [SMD1,27-2,54]  62.15,44.16 90 top
PC5T  WIREPAD2,54/0,8  [2,54/0,8]  87.53,118.96 270 top
PC5T1  WIREPAD2,54/0,8  [2,54/0,8]  109.23,118.96 270 top
PC5T2  WIREPAD2,54/0,8  [2,54/0,8]  129.28,118.89 270 top
PGNDT1  WIREPAD2,54/0,8  [2,54/0,8]  96.11,118.96 270 top
PGNDT2  WIREPAD2,54/0,8  [2,54/0,8]  117.81,118.96 270 top
PGNDT3  WIREPAD2,54/0,8  [2,54/0,8]  137.85,118.89 270 top
Q1  20MHz  [X22]  176.25,82.97 270 top
Q2  BSS138  [SOT23]  94.2,61.15 90 bottom
Q3  BSS138  [SOT23]  88.01,61.15 270 bottom
Q4  BSS138  [SOT23]  115.9,61.15 90 bottom
Q5  BSS138  [SOT23]  109.71,61.15 270 bottom
Q6  20MHz  [X22]  10.28,99.96 180 top
Q7  MOSFET-PCHANNEL  [SOT23]  157.01,113.1 0 top
Q8  MOSFET-PCHANNEL  [SOT23]  157.31,64.6 0 top
Q9  MOSFET-PCHANNEL  [SOT23]  157.31,80.9 0 top
Q10  MOSFET-PCHANNEL  [SOT23]  157.01,97.4 0 top
Q11  MOSFET-PCHANNEL  [SOT23]  135.95,105.36 180 top
Q12  MOSFET-PCHANNEL  [SOT23]  135.95,77.42 180 top
Q13  MOSFET-PCHANNEL  [SOT23]  135.95,86.72 180 top
Q14  MOSFET-PCHANNEL  [SOT23]  135.95,96.04 180 top
Q15  MOSFET-PCHANNEL  [SOT23]  135.95,68.1 180 top
Q16  20 Mhz  [X22]  127.03,41.66 270 top
Q17  MOSFET-PCHANNEL  [SOT23]  129.25,45.95 270 bottom
Q18  20 Mhz  [X22]  160.9,11.29 0 top
R1  10K  [0402-RES]  168.03,100.91 90 top
R2  100K  [0402-RES]  161.89,87.5 270 top
R3  100K  [0402-RES]  162.95,71.3 270 top
R4  100K  [0402-RES]  163.43,56.8 270 top
R5  100K  [0402-RES]  163.28,106.75 90 top
R6  0R27  [R1206]  148.11,105.9 90 top
R7  5.6k  [0805]  154.61,104.2 90 top
R8  47k  [0805]  160.01,110.4 90 top
R9  0R27  [R1206]  148.11,57 90 top
R10  5.6k  [0805]  154.91,56.1 90 top
R11  47k  [0805]  162.01,61.5 90 top
R12  0R27  [R1206]  148.21,73 90 top
R13  5.6k  [0805]  155.31,71.5 90 top
R14  47k  [0805]  161.71,76.7 90 top
R15  0R27  [R1206]  148.11,89.7 90 top
R16  5.6k  [0805]  154.91,87.9 90 top
R17  47k  [0805]  161.51,93.3 90 top
R18  100K  [R0402]  134.68,61.08 270 top
R19  100K  [R0402]  132.14,61.08 270 top
R20  10K  [0805]  69.29,61.14 270 top
R21  4K7  [0805]  67.46,61.14 270 top
R22  100K  [R0402]  129.6,61.08 270 top
R23  4K7  [0805]  65.64,61.14 270 top
R24  100K  [R0402]  127.06,61.08 270 top
R25  680  [0805]  72.15,49.95 180 top
R26  120  [0805]  72.07,54.95 90 top
R27  680  [0805]  72.07,59.95 0 top
R28  47R  [0805]  70.24,65.11 180 top
R29  47R  [0805]  67.07,64.4 0 top
R30  15k  [R0402]  85.31,24.4 90 top
R31  150R  [R0402]  96.41,30.9 270 top
R32  150R  [R0402]  103.91,22.8 0 top
R33  33R  [R0402]  96.01,23.4 180 bottom
R34  33R  [R0402]  96.21,21.5 90 bottom
R35  150R  [R0402]  89.61,29.7 90 top
R36  150R  [R0402]  88.31,29.7 90 top
R37  SE14  [SE14]  11.52,117.7 0 bottom
R38  10K  [0402-RES]  32.63,103.51 90 top
R39  100K  [0402-RES]  13.43,108.3 270 top
R40  100K  [0402-RES]  13.35,110.8 270 top
R41  100K  [0402-RES]  25.13,110.8 90 top
R42  100K  [0402-RES]  25.08,108.15 90 top
R43  150k  [0805]  35.91,87 0 top
R44  33k  [0805]  35.91,88.7 180 top
R45  150R  [0805]  115.84,52.61 0 top
R46  150R  [0805]  115.83,54.31 0 top
R47  150R  [0805]  96.81,45.6 90 top
R48  150R  [0805]  96.41,54.1 90 top
R49  150R  [0805]  85.21,45.3 270 top
R50  68k  [0805]  34.11,92 180 top
R51  18k  [0805]  35.91,90.4 180 top
R52  [MINI_MELF-0207R]  4.61,116.6 90 top
R53  [MINI_MELF-0207R]  17.41,113.6 0 top
R54  [MINI_MELF-0207R]  29.61,114.4 180 top
R55  [MINI_MELF-0207R]  31.71,117.8 180 top
R56  [MINI_MELF-0207R]  8.11,116.6 270 top
R57  68k  [0402-RES]  17.91,95.2 0 top
R58  150R  [0805]  18.51,11.5 180 top
R59  150R  [0805]  18.51,13.9 180 top
R60  10K  [0805]  18.51,6.4 270 top
R61  330R  [0805]  26.01,12.2 0 top
R62  330R  [0805]  26.01,14 0 top
R63  330R  [0805]  21.61,26.7 270 top
R64  0R27  [R1206]  128.45,104.61 0 bottom
R65  5.6k  [R0402]  140.52,104.1 180 top
R66  47k  [R0402]  138.8,112.04 0 top
R67  0R27  [R1206]  128.45,77.94 0 bottom
R68  5.6k  [R0402]  140.55,76.32 180 top
R69  47k  [R0402]  138.8,84.1 0 top
R70  0R27  [R1206]  128.45,86.76 0 bottom
R71  5.6k  [R0402]  140.55,85.53 180 top
R72  47k  [R0402]  138.8,93.46 0 top
R73  0R27  [R1206]  128.45,95.45 0 bottom
R74  5.6k  [R0402]  140.55,94.89 180 top
R75  47k  [R0402]  138.8,102.67 0 top
R76  0R27  [R1206]  128.45,69.09 0 bottom
R77  5.6k  [R0402]  140.55,66.95 180 top
R78  47k  [R0402]  138.8,74.89 0 top
R79  100K  [R0402]  137.22,61.08 270 top
R80  1k  [R0402]  136.6,49.91 180 top
R81  100R  [R0402]  135.53,36.26 270 top
R82  100R  [R0402]  133.78,36.9 270 top
R83  [R0805]  161.61,48.08 270 top
R84  1k  [R0402]  152.64,20.86 270 top
R85  100R  [R0402]  166.3,19.79 0 top
R86  100R  [R0402]  165.66,18.04 0 top
R87  1k  [R0402]  167.01,20.1 90 bottom
R88  1k  [R0402]  167.01,17.33 90 bottom
R89  [R0402]  129.46,21.83 180 top
R90  [R0402]  130.9,23.38 0 top
R91  [R0402]  140.47,23.4 180 top
R92  [R0402]  140.47,24.73 180 top
R93  [R0402]  130.9,24.74 0 top
R94  [R0402]  137.83,16.19 270 bottom
R95  [R0402]  137.86,19.76 90 bottom
R96  [R0402]  73.28,7.36 0 top
R97  [R0402]  78.66,13.86 270 top
R+  SE14  [SE14]  145.11,65.7 90 top
R+1  SE14  [SE14]  124.01,111.26 270 top
R-  SE14  [SE14]  145.11,58.5 90 top
R-1  SE14  [SE14]  124.01,105.03 270 top
R_B  tbs  [0805]  92.3,60.35 0 top
R_B1  tbs  [0805]  114,60.35 0 top
R_G  tbs  [0805]  88.28,60.35 0 top
R_G1  tbs  [0805]  109.98,60.35 0 top
R_R  tbs  [0805]  81.82,112.14 90 top
R_R1  tbs  [0805]  103.52,112.14 90 top
R_U  tbs  [1206]  97.17,60.67 0 top
R_U1  tbs  [1206]  118.87,60.67 0 top
R_W  tbs  [1206]  83.45,60.67 180 top
R_W1  tbs  [1206]  105.15,60.67 180 top
RD1  [LED5MM]  82.92,107.06 270 top
RD2  [LED5MM]  97.86,110.22 270 top
RD3  [LED5MM]  92.88,100.73 270 top
RD4  [LED5MM]  87.9,97.56 270 top
RD5  [LED5MM]  92.88,81.74 270 top
RD6  [LED5MM]  87.9,78.57 270 top
RD7  [LED5MM]  97.86,72.24 270 top
RD8  [LED5MM]  82.92,69.08 270 top
RD9  [LED5MM]  104.62,107.06 270 top
RD10  [LED5MM]  119.56,110.22 270 top
RD11  [LED5MM]  114.58,100.73 270 top
RD12  [LED5MM]  109.6,97.56 270 top
RD13  [LED5MM]  114.58,81.74 270 top
RD14  [LED5MM]  109.6,78.57 270 top
RD15  [LED5MM]  104.62,69.08 270 top
RD16  [LED5MM]  119.56,72.24 270 top
RST  SWITCH_MCTAEF  [SWITCH_MCTAEF]  82.41,29.4 90 top
RX1  [CHIP-LED0805]  15.01,11.5 90 top
RX2  [CHIP-LED0805]  111.95,52.56 90 top
RXD1  [SMD1,27-2,54]  82.61,47.63 270 top
S1  BIND  [TACTILE_SWITCH_SMD]  177.01,24.63 270 bottom
S4  [TACTILE_SWITCH_SMD]  135.37,31.9 0 bottom
SBUS  [1X03_LONGPADS]  173.84,6.06 90 top
SG4  F/CM12P  [F/CM12P]  140.26,15.05 90 bottom
SJ1  [SJ_2S-NO]  73.58,84.32 90 top
SJ2  [SJ_2S-NO]  71.59,84.32 90 top
SJ3  [SJ_2S-NO]  69.61,84.32 90 top
SJ4  [SJ_2S-NO]  67.62,84.32 90 top
SJ5  [SJ_2S-NO]  65.64,84.32 90 top
SJ6  [SJ_2S-NO]  63.65,84.32 90 top
SJ7  [SJ_2S-NO]  61.67,84.32 90 top
SJ8  [SJ_2S-NO]  72.31,52.17 180 top
SJ9  [SJ_2S-NO]  72.15,57.73 180 top
SPEKTRUM_TX  [1X04_LONGPADS]  148.67,5.74 90 top
SV1  [FE05-2]  149.42,47.4 0 bottom
SV2  [MA04-1]  127.61,6.3 180 top
SW1  MCMT5-F-VADAPTED_FOOTPRINT  [MCMT5-F-V_ADAPTED]  71.04,112.58 45 top
SW2  SWITCH_MCTAEF  [SWITCH_MCTAEF]  101.51,25.7 0 top
SW3  [SMD2,54-5,08]  63.84,11.09 90 bottom
SW4  [SMD2,54-5,08]  63.93,7.79 270 bottom
T3  IRF7103  [SO-8]  8.9,108.87 180 top
T4  IRF7103  [SO-8]  29.46,110.08 0 top
TX1  [CHIP-LED0805]  15.01,13.9 90 top
TX2  [CHIP-LED0805]  111.95,54.34 90 top
TXD1  [SMD1,27-2,54]  82.61,52.71 270 top
U1  NICHIA_NSSL157T-H3  [PLCC2]  97.85,103.89 90 top
U1A  [LED5MM]  97.86,103.89 270 top
U1A1  [LED5MM]  119.56,103.89 270 top
U2  NICHIA_NSSL157T-H3  [PLCC2]  97.85,91.23 90 top
U2A  [LED5MM]  97.86,91.23 270 top
U2A1  [LED5MM]  119.56,91.23 270 top
U3  NICHIA_NSSL157T-H3  [PLCC2]  82.94,94.41 90 top
U3A  [LED5MM]  82.92,94.4 270 top
U3A1  [LED5MM]  104.62,94.4 270 top
U4  NICHIA_NSSL157T-H3  [PLCC2]  82.94,81.75 90 top
U4A  [LED5MM]  82.92,81.74 270 top
U4A1  [LED5MM]  104.62,81.74 270 top
U5  NICHIA_NSSL157T-H3  [PLCC2]  97.85,78.57 90 top
U5A  [LED5MM]  97.86,78.57 270 top
U5A1  [LED5MM]  119.56,78.57 270 top
U6  NICHIA_NSSL157T-H3  [PLCC2]  119.55,103.89 90 top
U7  NICHIA_NSSL157T-H3  [PLCC2]  119.55,91.23 90 top
U8  NICHIA_NSSL157T-H3  [PLCC2]  119.55,78.57 90 top
U9  NICHIA_NSSL157T-H3  [PLCC2]  104.64,81.75 90 top
U10  NICHIA_NSSL157T-H3  [PLCC2]  104.64,94.41 90 top
U$1  USB-MINIB-5PIN  [USB-MINIB]  101.31,22.2 0 bottom
U$2  SP0503BAHTG  [SOT143-R]  167.63,35.81 0 top
U$3  CP2105REAL  [S-PQFP-N24(RGE)]  160.82,40.34 180 top
U+  SE14  [SE14]  124.01,74.02 270 top
U-  SE14  [SE14]  124.01,67.8 270 top
VCC  [SMD2,54-5,08]  161.77,6.21 270 bottom
VCC1  [SMD2,54-5,08]  63.84,7.91 90 top
W1  NICHIA_NSSL157T-H3  [NICHIA_NSSL157T-H3]  97.86,84.9 90 top
W1A  [LED5MM]  97.86,84.9 270 top
W1A1  [LED5MM]  119.56,84.9 270 top
W2  NICHIA_NSSL157T-H3  [NICHIA_NSSL157T-H3]  97.86,97.56 90 top
W2A  [LED5MM]  97.86,97.56 270 top
W2A1  [LED5MM]  119.56,97.56 270 top
W3  NICHIA_NSSL157T-H3  [NICHIA_NSSL157T-H3]  82.92,100.73 90 top
W3A  [LED5MM]  82.92,100.73 270 top
W3A1  [LED5MM]  104.62,100.73 270 top
W4  NICHIA_NSSL157T-H3  [NICHIA_NSSL157T-H3]  82.92,88.07 90 top
W4A  [LED5MM]  82.92,88.07 270 top
W4A1  [LED5MM]  104.62,88.07 270 top
W5  NICHIA_NSSL157T-H3  [NICHIA_NSSL157T-H3]  82.92,75.41 90 top
W5A  [LED5MM]  82.92,75.41 270 top
W5A1  [LED5MM]  104.62,75.41 270 top
W6  NICHIA_NSSL157T-H3  [NICHIA_NSSL157T-H3]  119.56,97.56 90 top
W7  NICHIA_NSSL157T-H3  [NICHIA_NSSL157T-H3]  119.56,84.9 90 top
W8  NICHIA_NSSL157T-H3  [NICHIA_NSSL157T-H3]  104.62,75.41 90 top
W9  NICHIA_NSSL157T-H3  [NICHIA_NSSL157T-H3]  104.62,88.07 90 top
W10  NICHIA_NSSL157T-H3  [NICHIA_NSSL157T-H3]  104.62,100.73 90 top
W11  SE14  [SE14]  26.47,117.7 0 top
W+  SE14  [SE14]  145.11,114.55 90 top
W+1  SE14  [SE14]  124.01,83.32 270 top
W-  SE14  [SE14]  145.11,107.3 90 top
W-1  SE14  [SE14]  124.01,77.12 270 top
X1  RJ45-8L-B  [RJ45-NO-SHIELD]  172.05,114.66 180 top
X2  RJ45-8L-B  [RJ45-NO-SHIELD]  172.05,57.89 0 top
X3  MINI-USB-32005-301  [32005-301]  176.31,40.43 180 top
X4  2510-  [PAK100/2500-10]  149.77,34.5 0 bottom
X8  RJ45-8L-B  [RJ45-NO-SHIELD]  50.31,9.5 0 top
X9  RJ45-8L-B  [RJ45-NO-SHIELD]  50.31,116.5 180 top
X10  20 MHz  [HC49UP-SMALL]  77.39,84.32 270 top
X11  RJ45-8L-B  [RJ45-NO-SHIELD]  34.77,75.46 90 top
X12  USB-SMD-NS  [USB-MINIB-NOSTOP]  114.93,45.81 180 top
X13  RJ45-8L-B  [RJ45-NO-SHIELD]  8.1,75.71 270 top
X14  RJ45-8L-B  [RJ45-NO-SHIELD]  5.51,54.9 270 top
X15  RJ45-8L-B  [RJ45-NO-SHIELD]  37.21,54.9 90 top
X16  RJ45-8L-B  [RJ45-NO-SHIELD]  8.11,34.2 270 top
X17  RJ45-8L-B  [RJ45-NO-SHIELD]  34.81,34.2 90 top
X18  USB-SMD-NS  [USB-MINIB-NOSTOP]  34.41,10 90 top
XL  RJ45  [85502-5008-SMALL]  70.33,28.44 90 top
XR  RJ45  [85502-5008-SMALL]  70.33,112.58 270 top

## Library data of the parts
5V 5V1 +18_L +18_R A_L A_R ADC6 ADC7 B_L B_R C C_L D D_L GND GND2-GND4 GND_L GND_R LED+ LED- OUT P+5T P+5T1 P+5T2 P+18T P+18T1 P+18T2 PAD1-PAD5 PB0 PB1 PB1T PB1T1 PB1T2 PB2-PB5 PC0 PC1-PC3 PC3T PC3T1 PC3T2 PC4 PC4T PC4T1 PC4T2 PC5 PC5T PC5T1 PC5T2 PGNDT1-PGNDT3 RXD1 SW3 SW4 TXD1 VCC VCC1 = wirepad
+1 +5V1 B11 B+ B+1 B- B-1 G11 G+ G+1 G- G-1 GND1 R37 R+ R+1 R- R-1 U+ U- W11 W+ W+1 W- W-1 = solpad
B1-B10 G1-G10 JP1 RD1-RD16 U1A U1A1 U2A U2A1 U3A U3A1 U4A U4A1 U5A U5A1 W1A W1A1 W2A W2A1 W3A W3A1 W4A W4A1 W5A W5A1 X10 XL XR = Alex_personal
BIND FRAME LED1-LED8 RX1 RX2 TX1 TX2 = led
BL/SW2 D3-D10 IC3 IC6-IC8 IC11 IC16 IC21-IC25 IC31 L1-L4 L8 L9 L15 Q1 Q6 Q16 Q18 RST SW2 U1-U10 W1-W10 = seb
C1-C5 C7 C9 C11-C13 C15 C17 C18 C20 C22 C23 C25-C36 C42 C43 C45-C55 C57-C68 C70-C73 C75 C76 C79 C85 C88 C91 C94 C95 C100 C101 IC14 IC19 JP5 JP6 Q7-Q15 Q17 R1-R5 R7 R8 R10 R11 R13 R14 R16 R17 R20 R21 R23 R25-R29 R38-R51 R57-R63 R_B R_B1 R_G R_G1 R_R R_R1 R_U R_U1 R_W R_W1 S1 S4 SBUS SJ1-SJ9 SPEKTRUM_TX U$1 X12 X18 = SparkFun
C6 C8 C10 C14 C16 C19 C21 C24 C37-C41 C44 C74 C77 C78 C80 C82-C84 C86 C87 C89 C93 C96-C99 C102 C103 R6 R9 R12 R15 R18 R19 R22 R24 R30-R36 R52-R56 R64-R97 = rcl
C56 C69 C81 C90 C92 = resistor
D1 D2 D11-D18 = diode
IC1 IC15 IC32 = avr-7
IC2 IC13 IC20 = maxim; MF: MAXIM; MPN: MAX481CSA; OC_FARNELL: unknown; OC_NEWARK: 90C3817
IC4 IC10 IC17 IC18 IC33 = linear
IC5 = atmel; MPN: ATMEGA8-16AU; OC_FARNELL: 9171371; OC_NEWARK: 73M8863
IC9 = Alex_personal; MF: MAXIM; MPN: MAX487; OC_FARNELL: unknown; OC_NEWARK: unknown
IC12 = microbuilder; DIGIKEY#: 568-4945-ND; MANF: NXP; MANF#: LPC1343FBD48,151
IC26 IC28 = avr-4
IC27 = linear-technology
IC29 = linear-technology; MPN: LT1763CS8-1.5; OC_FARNELL: 1501016; OC_NEWARK: 57M6043
IC30 = linear-technology; MPN: LT1763CS8-3.3; OC_FARNELL: 1273617; OC_NEWARK: 57M6055
IC34 = atmel; MPN: ATTINY13V-10SU; OC_FARNELL: 9171584; OC_NEWARK: 96K6524
ISP ISP1 = atmel
ISP2 JP2 JP3 JP3A JP3B JP4 = pinhead-2
JP1T JP1T1 JP1T2 JP2T JP2T1 JP2T2 SV1 = con-lsta; OC_FARNELL: unknown; OC_NEWARK: unknown
L1A1 = seb; FARNELL: 1741367
L5 = seb; FARNELL: 1669987
L6 L7 = rc-master-smd
L10-L14 = wuerth-elektronik
OK4-OK8 = optocoupler; MF: AGILENT TECHNOLOGIES; MPN: HCPL-0601-000E; OC_FARNELL: 9995102; OC_NEWARK: 88H7776
Q2-Q5 = transistor-small-signal
SG4 = buzzer; OC_FARNELL: unknown; OC_NEWARK: unknown
SV2 = con-lstb; OC_FARNELL: unknown; OC_NEWARK: unknown
SW1 = alex3
T3 T4 = transistor-fet+irf7201
U$2 U$3 = pentabridgeparts
X1 X2 X8 X9 X11 X13-X17 = con-tycoelectronics; MF: TYCO ELECTRONICS; MPN: RJ45-8L-B; OC_FARNELL: 1279843; OC_NEWARK: 52K4445
X3 = con-cypressindustries; OC_FARNELL: unknown; OC_NEWARK: unknown
X4 = con-3m; MF: 3M; MPN: 2510-6002UB; OC_FARNELL: 9838244; OC_NEWARK: 46F4725

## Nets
1.8V: C92.+ C93.1 IC29.1 R87.2 SPEKTRUM_TX.4
1_4: IC12.40 JP4.7
1_5: IC12.45 JP4.6
2_6: IC12.1 JP4.2
3.3V: C76.1 C80.1 C81.+ IC26.4 IC26.6 IC27.1 IC27.2 LED3.A LED4.A Q17.2 R80.1
3.3V1: BIND.A C85.1 C95.1 C96.1 FRAME.A IC28.4 IC28.6 IC31.5 R84.1 SPEKTRUM_TX.3
3_3: IC12.48 JP4.3
5V: C79.1 IC27.5 IC27.8 JP6.2
7.4V: C88.1 IC30.5 IC30.8 VCC.1
!RE: IC1.9 IC2.2 IC2.3
!RE2: IC13.2 IC13.3 IC15.9
!RE3: IC20.2 IC20.3 OK8.6
!RST: IC1.29 ISP.5 R1.1
!RST1: IC15.29 ISP1.5 R38.1
+3V1: C40.2 C41.2 C43.1 C44.1 IC11.5 IC12.8 IC12.44 JP4.9 R30.2 R31.1 R32.2
+3V2: +5V1.MP C51.1 IC16.1 L1A1.P$1 L5.P$1 R43.2
+5V: C1.1 C2.1 C3.1 C12.2 IC1.4 IC1.6 IC1.18 IC2.8 IC4.1 ISP.2 R1.2
+5V1: 5V.1 C89.1 C90.+ C91.1 C94.1 IC29.5 IC29.8 IC30.1 IC30.2 IC31.1 IC31.3 SBUS.2
+5V2: C42.1 IC11.1 IC11.3 JP4.10 U$1.VBUS
+5V3: C47.1 C48.1 C49.1 C63.2 IC13.8 IC15.4 IC15.6 IC15.18 IC17.1 ISP1.2 R38.2
+5V4: C54.1 C56.+ C57.2 IC14.4 IC14.20 L6.2 OK6.2 OK7.8 R45.2 R46.2 R47.1
+5V5: C65.2 C71.1 C72.1 C73.1 IC18.1 IC20.8 OK4.7 OK4.8 OK8.7 OK8.8 R63.1
+5V6: C97.2 C101.2 C102.2 IC32.4 IC32.6 IC33.1 ISP2.2 L15.1 R89.2 R90.1 R91.1 R92.1 R93.1 SG4.-
+12V: C6.1 C8.1 C10.1 C13.2 C14.1 IC3.7 IC4.8 IC6.7 IC7.7 IC8.7 Q7.2 Q8.2 Q9.2 Q10.2 R8.2 R11.2 R14.2 R17.2 X1.4 X1.5 X2.4 X2.5
+12V1: C59.1 C60.1 C61.1 C62.2 IC16.4 IC17.8 X11.4 X11.5 X13.4 X13.5
+12V2: C100.2 IC33.8 R95.2 SV2.4
+18V: C16.1 C19.1 C21.1 C24.1 C74.1 IC21.7 IC22.7 IC23.7 IC24.7 IC25.7 JP1T2.7 P+18T2.1 Q11.2 Q12.2 Q13.2 Q14.2 Q15.2 R66.2 R69.2 R72.2 R75.2 R78.2
+18V1: +18_L.1 +18_R.1 C32.1 C37.+ IC10.8 JP1.7 PAD2.1 XL.4 XL.5 XR.4 XR.5
+18V2: +1.MP D11.A
+18V_PI1: D11.C X14.4 X14.5 X15.4 X15.5
+24V1: C64.2 IC18.8 X16.4 X16.5 X17.4 X17.5
+24V_SB: C23.+ C26.+ C27.+ C28.+ C29.+ C30.+ X8.4 X8.5 X9.4 X9.5
+USB_SIEVED1: C67.1 C69.+ C70.2 IC19.4 IC19.20 L7.2 OK5.7 OK5.8 R58.1 R59.1 R60.1 R61.1 R62.1
_VCC: JP2T.2 P+5T.1
_VCC1: JP2T1.2 P+5T1.1
_VCC2: JP2T2.2 P+5T2.1
A: IC2.6 X1.3 X2.3
A1_1: X8.3 X9.3
A2: IC13.6 X11.3 X13.3
A3: IC20.6 X16.3 X17.3
A_PI1: X14.3 X15.3
ADC0: IC5.23 PC0.1 SW1.1
ADC1: IC5.24 PC1.1 SW1.6
ADC2: IC5.25 PC2.1 SW1.4
ADR_DEC: IC5.12 PB0.1 SJ1.1 SJ2.1 SJ3.1 SJ4.1 SJ5.1 SJ6.1 SJ7.1
AGND: IC26.21
B: IC2.7 X1.6 X2.6
B1: JP2T2.3 PB1T2.1
B1_1: X8.6 X9.6
B2: JP2T.3 PB1T.1
B3: JP2T1.3 PB1T1.1
B4: IC13.7 X11.6 X13.6
B5: IC20.7 X16.6 X17.6
B_PI1: X14.6 X15.6
C3/ADC1: JP2T1.6 PC3T1.1
C3/ADC2: JP2T2.6 PC3T2.1
C3/ADC3: JP2T.6 PC3T.1
C4/ADC4/SDA: JP2T.5 PC4T.1
C4/ADC4/SDA1: JP2T1.5 PC4T1.1
C4/ADC4/SDA2: JP2T2.5 PC4T2.1
C5/ADC5/SCL: JP2T.4 PC5T.1
C5/ADC5/SCL1: JP2T1.4 PC5T1.1
C5/ADC5/SCL2: JP2T2.4 PC5T2.1
CTS_E: SV1.2 U$3.10
CTS_S: U$3.18 X4.8
DCD_S: U$3.24 X4.1
DSR_E: SV1.6 U$3.14
DSR_S: U$3.22 X4.6
DTR_E: SV1.8 U$3.15
DTR_S: U$3.23 X4.4
GND: C1.2 C2.2 C3.2 C4.1 C5.1 C6.2 C8.2 C10.2 C12.1 C13.1 C14.2 D1.A D2.A D12.A D13.A IC1.3 IC1.5 IC1.21 IC2.5 IC3.5 IC4.2 IC4.3 IC4.6 IC4.7 IC6.5 IC7.5 IC8.5 ISP.6 R2.2 R3.2 R4.2 R5.2 R6.1 R7.1 R9.1 R10.1 R12.1 R13.1 R15.1 R16.1 X1.1 X1.2 X2.1 X2.2
GND1: C18.1 C31.1 C32.2 C33.2 C34.2 C35.1 C36.1 C37.- GND_L.1 GND_R.1 IC5.3 IC5.5 IC5.21 IC9.5 IC10.2 IC10.3 IC10.6 IC10.7 JP1.1 JP2.1 JP3A.6 JP3B.6 PAD1.1 PAD5.1 R27.2 SW1.5 SW1.TAB1 SW1.TAB2 XL.1 XL.2 XR.1 XR.2
GND2: BL/SW2.1 C38.1 C39.1 C40.1 C41.1 C42.2 C43.2 IC11.2 IC12.5 IC12.41 JP4.8 RST.1 SW2.2 U$1.GND U$1.MTN1 U$1.MTN2 U$1.MTN3 U$1.MTN4
GND3: C45.1 C46.1 C47.2 C48.2 C49.2 C50.1 C51.2 C59.2 C60.2 C61.2 C62.1 C63.1 D10.A IC13.5 IC15.3 IC15.5 IC15.21 IC16.6 IC16.PAD IC17.2 IC17.3 IC17.6 IC17.7 ISP1.6 R39.2 R40.2 R41.2 R42.2 R44.1 R50.1 R57.1 T3.1 T3.3 T4.1 T4.3 X11.1 X11.2 X13.1 X13.2
GND4: C53.2 C54.2 C55.2 C56.- C57.1 IC14.7 IC14.18 IC14.21 IC14.25 IC14.26 OK7.5 X12.GND
GND5: C76.2 C77.1 C78.1 C79.2 C81.- IC26.3 IC26.5 IC27.3 IC27.6 IC27.7 JP5.1 JP6.1 S4.3 S4.4
GND6: C82.1 C83.1 C84.1 SV1.7 U$2.1 U$3.2 X3.5 X4.5
GND7: C85.2 C86.1 C87.1 C88.2 C90.- C91.2 C92.- C94.2 C95.2 GND.1 IC28.3 IC28.5 IC28.21 IC29.3 IC29.6 IC29.7 IC30.3 IC30.6 IC30.7 IC31.2 R88.1 S1.3 S1.4 SBUS.1 SPEKTRUM_TX.1
GND8: C97.1 C98.1 C99.1 C100.1 C101.1 IC32.3 IC32.5 IC32.21 IC33.2 IC33.3 IC33.6 IC33.7 ISP2.6 R94.2 SV2.1
GND9: C103.1 GND3.1 GND4.1 IC34.4
GND_AL1: C64.1 C65.1 C71.2 C72.2 C73.2 IC18.2 IC18.3 IC18.6 IC18.7 IC20.5 OK4.5 OK8.5 X16.1 X16.2 X17.1 X17.2
GND_PI1: GND1.MP X14.1 X14.2 X15.1 X15.2
GND_SB: C23.- C26.- C27.- C28.- C29.- C30.- X8.1 X8.2 X9.1 X9.2
GND_T: JP1T.1 JP2T.1 PGNDT1.1 Q2.2 Q3.2
GND_T1: JP1T1.1 JP2T1.1 PGNDT2.1 Q4.2 Q5.2
GND_T2: C16.2 C19.2 C21.2 C24.2 C74.2 D14.A D15.A D16.A D17.A D18.A IC21.5 IC22.5 IC23.5 IC24.5 IC25.5 JP1T2.1 JP2T2.1 PGNDT3.1 R18.2 R19.2 R22.2 R24.2 R64.1 R65.1 R67.1 R68.1 R70.1 R71.1 R73.1 R74.1 R76.1 R77.1 R79.2
GND_USB1: C66.2 C67.2 C68.2 C69.- C70.1 IC19.7 IC19.18 IC19.21 IC19.25 IC19.26 OK5.5 X18.GND
LED_B: D3.1 IC5.9 JP1.4
LED_G: D4.1 IC5.2 JP1.3
LED_R: D5.1 IC5.1 JP1.2
LED_U: D9.1 IC5.11 JP1.6
LED_W: D8.1 IC5.10 JP1.5
MISO: IC1.16 ISP.1
MISO1: IC5.16 JP3A.1 JP3B.1 PB4.1
MISO2: IC15.16 ISP1.1
MISO3: IC32.16 ISP2.1
MOSI: IC1.15 ISP.4
MOSI1: IC5.15 JP3A.4 JP3B.4 PB3.1
MOSI2: IC15.15 ISP1.4
MOSI3: IC32.15 ISP2.4
N$1: C7.1 IC3.3 R6.2 W-.MP
N$2: C7.2 L1.P$2 W+.MP
N$3: D2.C IC3.1 L1.P$1 Q7.3
N$4: C9.1 IC6.3 R9.2 R-.MP
N$5: IC3.4 R7.2
N$6: C9.2 L2.P$2 R+.MP
N$7: IC3.8 R8.1
N$8: D1.C IC6.1 L2.P$1 Q8.3
N$9: IC6.4 R10.2
N$10: IC3.6 Q7.1
N$11: IC6.8 R11.1
N$12: IC6.6 Q8.1
N$13: C11.1 G-.MP IC7.3 R12.2
N$14: C11.2 G+.MP L8.P$2
N$15: D12.C IC7.1 L8.P$1 Q9.3
N$16: IC7.4 R13.2
N$17: IC7.8 R14.1
N$18: X1.7 X2.7
N$19: X1.8 X2.8
N$20: IC7.6 Q9.1
N$21: B-.MP C15.1 IC8.3 R15.2
N$22: B+.MP C15.2 L9.P$2
N$23: D13.C IC8.1 L9.P$1 Q10.3
N$24: IC8.4 R16.2
N$25: IC8.8 R17.1
N$26: IC8.6 Q10.1
N$29: C17.1 IC21.3 R64.2 R-1.MP
N$30: C17.2 L10.1 R+1.MP
N$31: D14.C IC21.1 L10.2 Q11.3
N$32: IC21.4 R65.2
N$33: X8.8 X9.8
N$34: X8.7 X9.7
N$35: IC21.8 R66.1
N$36: IC5.30 IC9.1
N$37: IC21.6 Q11.1
N$38: C18.2 IC5.8 X10.2
N$39: C31.2 IC5.7 X10.1
N$40: ADC6.1 IC5.19
N$41: ADC7.1 IC5.22
N$42: C35.2 IC5.18 L3.2
N$43: C36.2 IC5.20
N$44: C20.1 IC22.3 R67.2 W-1.MP
N$45: D7.2 SJ1.2
N$46: D6.2 SJ2.2
N$47: D5.2 SJ3.2
N$48: D4.2 SJ4.2
N$49: R25.2 R26.1 SJ8.2
N$50: D3.2 SJ5.2
N$51: D8.2 SJ6.2
N$52: D9.2 SJ7.2
N$53: R26.2 R27.1 SJ9.2
N$54: IC5.28 R29.2
N$55: IC5.14 PB2.1
N$56: C.1 C_L.1 XL.7 XR.7
N$57: D.1 D_L.1 XL.8 XR.8
N$58: R_W.2 W5.K@1 W5A.K
N$59: IC5.27 R28.2
N$60: U1.P$1 U1A.K U2.P$2 U2A.A
N$61: G1.K G2.A
N$62: G2.K G3.A
N$63: G3.K G4.A
N$64: G4.K G5.A
N$65: G5.K R_G.2
N$66: B1.K B2.A
N$67: B2.K B3.A
N$68: B3.K B4.A
N$69: B4.K B5.A
N$70: B5.K R_B.2
N$71: RD1.K RD2.A
N$72: RD2.K RD3.A
N$73: RD3.K RD4.A
N$74: RD4.K RD5.A
N$75: RD5.K RD6.A
N$76: Q3.3 R_W.1
N$77: JP1T.6 Q2.1
N$78: JP1T.5 Q3.1
N$79: JP1T.3 R_G.1
N$80: JP1T.4 R_B.1
N$81: JP1T.2 RD8.K
N$82: R_R.1 RD1.A
N$83: RD6.K RD7.A
N$84: RD7.K RD8.A
N$85: W4.K@1 W4A.K W5.A@2 W5A.A
N$86: W3.K@1 W3A.K W4.A@2 W4A.A
N$87: W2.K@1 W2A.K W3.A@2 W3A.A
N$88: W1.K@1 W1A.K W2.A@2 W2A.A
N$89: R_U.2 U5.P$1 U5A.K
N$90: U4.P$1 U4A.K U5.P$2 U5A.A
N$91: U3.P$1 U3A.K U4.P$2 U4A.A
N$92: U2.P$1 U2A.K U3.P$2 U3A.A
N$93: Q2.3 R_U.1
N$94: R_W1.2 W5A1.K W8.K@1
N$95: U1A1.K U2A1.A U6.P$1 U7.P$2
N$96: G6.K G7.A
N$97: G7.K G8.A
N$98: G8.K G9.A
N$99: G9.K G10.A
N$100: G10.K R_G1.2
N$101: B6.K B7.A
N$102: B7.K B8.A
N$103: B8.K B9.A
N$104: B9.K B10.A
N$105: B10.K R_B1.2
N$106: RD9.K RD10.A
N$107: RD10.K RD11.A
N$108: RD11.K RD12.A
N$109: RD12.K RD13.A
N$110: RD13.K RD14.A
N$111: Q5.3 R_W1.1
N$112: JP1T1.6 Q4.1
N$113: JP1T1.5 Q5.1
N$114: JP1T1.3 R_G1.1
N$115: JP1T1.4 R_B1.1
N$116: JP1T1.2 RD15.K
N$117: R_R1.1 RD9.A
N$118: RD14.K RD16.A
N$119: RD15.A RD16.K
N$120: W4A1.K W5A1.A W8.A@2 W9.K@1
N$121: W3A1.K W4A1.A W9.A@2 W10.K@1
N$122: W2A1.K W3A1.A W6.K@1 W10.A@2
N$123: W1A1.K W2A1.A W6.A@2 W7.K@1
N$124: R_U1.2 U5A1.K U8.P$1
N$125: U4A1.K U5A1.A U8.P$2 U9.P$1
N$126: U3A1.K U4A1.A U9.P$2 U10.P$1
N$127: U2A1.K U3A1.A U7.P$1 U10.P$2
N$128: Q4.3 R_U1.1
N$129: C38.2 IC12.7 L4.1
N$130: C39.2 IC12.6 L4.3
N$131: IC12.3 JP4.1 R30.1 RST.2
N$132: IC12.32 JP3.1
N$133: IC12.29 JP3.2
N$134: IC12.28 JP3.3
N$135: IC12.27 JP3.4
N$136: IC12.23 JP3.5
N$137: IC12.22 JP3.6
N$138: IC12.14 JP3.9
N$139: IC12.10 JP3.10
N$140: C44.2 IC11.4
N$141: LED1.A R31.2
N$142: IC12.36 LED1.C
N$143: BL/SW2.2 IC12.4
N$144: IC12.35 SW2.1
N$145: LED2.A R32.1
N$146: IC12.33 LED2.C
N$147: R34.2 U$1.D+
N$148: R33.2 U$1.D-
N$149: IC12.19 R33.1
N$150: IC12.20 R34.1
N$151: IC12.46 R35.1
N$152: IC12.47 R36.1
N$153: R52.1 T3.8
N$154: R53.1 T3.5
N$155: R54.1 T4.8
N$156: G11.MP R53.2
N$157: B11.MP R54.2
N$158: R55.2 W11.MP
N$159: R55.1 T4.5
N$160: IC16.10 R50.2
N$161: C50.2 R51.1
N$162: IC16.9 R51.2
N$163: C52.1 D10.K IC16.3 L1A1.P$2 L5.P$2
N$164: IC16.8 R43.1 R44.2
N$165: C52.2 IC16.2
N$166: IC15.12 IC16.5 R57.2
N$167: R52.2 R56.1
N$168: R37.MP R56.2
N$169: IC14.16 X12.D-
N$170: IC14.15 X12.D+
N$171: R45.1 RX2.A
N$172: R46.1 TX2.A
N$173: C55.1 IC14.17
N$174: IC14.22 RX2.C
N$175: IC14.23 TX2.C
N$176: C53.1 L6.1 X12.VBUS
N$178: IC14.14 R47.2
N$179: C58.2 GND2.1 OK6.5
N$180: 5V1.1 C58.1 OK6.8 OK7.3
N$181: OK6.6 TXD1.1
N$182: OK6.3 R48.1
N$183: OK7.2 R49.2
N$184: R49.1 RXD1.1
N$185: X11.7 X13.7
N$186: X11.8 X13.8
N$187: X14.7 X15.7
N$188: X14.8 X15.8
N$189: X16.8 X17.8
N$190: X16.7 X17.7
N$191: IC19.16 X18.D-
N$192: IC19.15 X18.D+
N$193: R58.2 RX1.A
N$194: R59.2 TX1.A
N$195: C68.1 IC19.17
N$196: IC19.22 RX1.C
N$197: IC19.23 TX1.C
N$198: C66.1 L7.1 X18.VBUS
N$199: IC19.14 R60.2
N$200: OK5.2 R63.2
N$201: OK4.2 R61.2
N$202: OK8.2 R62.2
N$203: IC19.13 OK8.3
N$204: C20.2 L11.1 W+1.MP
N$205: D15.C IC22.1 L11.2 Q12.3
N$206: IC22.4 R68.2
N$207: IC22.8 R69.1
N$208: IC22.6 Q12.1
N$209: B-1.MP C22.1 IC23.3 R70.2
N$210: B+1.MP C22.2 L12.1
N$211: D16.C IC23.1 L12.2 Q13.3
N$212: IC23.4 R71.2
N$213: IC23.8 R72.1
N$214: IC23.6 Q13.1
N$215: C25.1 G-1.MP IC24.3 R73.2
N$216: C25.2 G+1.MP L13.1
N$217: D17.C IC24.1 L13.2 Q14.3
N$218: IC24.4 R74.2
N$219: IC24.8 R75.1
N$220: IC24.6 Q14.1
N$221: C75.1 IC25.3 R76.2 U-.MP
N$222: C75.2 L14.1 U+.MP
N$223: D18.C IC25.1 L14.2 Q15.3
N$224: IC25.4 R77.2
N$225: IC25.8 R78.1
N$226: IC25.6 Q15.1
N$227: IC26.29 R80.2
N$228: C78.2 IC26.8 Q16.1
N$229: C77.2 IC26.7 Q16.3
N$230: IC26.14 JP6.3
N$231: LED3.C R81.2
N$232: IC26.13 R81.1
N$233: IC26.30 JP5.3
N$234: C80.2 IC27.4
N$235: IC26.15 S4.1 S4.2
N$236: IC26.1 Q17.1
N$237: JP5.2 Q17.3
N$238: LED4.C R82.2
N$239: IC26.10 R82.1
N$240: U$2.4 U$3.4 X3.2
N$241: U$2.2 U$3.3 X3.3
N$242: R83.2 U$3.9
N$243: IC28.29 R84.2
N$244: C87.2 IC28.8 Q18.1
N$245: C86.2 IC28.7 Q18.3
N$246: FRAME.C R85.2
N$247: IC28.13 R85.1
N$248: C89.2 IC30.4
N$249: IC28.15 S1.1 S1.2
N$250: BIND.C R86.2
N$251: IC28.10 R86.1
N$252: C93.2 IC29.4
N$253: C96.2 IC31.4
N$254: IC28.30 SBUS.3
N$255: IC29.2 R87.1 R88.2
N$256: C99.2 IC32.20
N$257: C98.2 IC32.18 L15.2
N$258: LED5.A R93.2
N$259: LED6.A R92.2
N$260: LED7.A R91.2
N$261: LED8.A R90.2
N$262: C102.1 IC32.11 SG4.+
N$263: IC32.24 LED7.C
N$264: IC32.25 LED6.C
N$265: IC32.26 LED5.C
N$266: IC32.23 R94.1 R95.1
N$267: IC32.27 LED8.C
N$268: IC34.1 R96.2
N$269: IC34.3 R97.2
N$270: LED-.1 R97.1
N$271: IC34.5 OUT.1
N$272: IC34.6 SW3.1
N$273: IC34.7 SW4.1
PB: IC1.26 IC8.2 R2.1
PB1: IC15.26 R41.1 T4.2
PG: IC1.27 IC7.2 R3.1
PG1: IC15.27 R40.1 T3.4
PR: IC1.28 IC6.2 R4.1
PR1: IC15.28 R39.1 T3.2
PW: IC1.25 IC3.2 R5.1
PW1: IC15.25 R42.1 T4.4
RE/DE: D6.1 IC5.32 IC9.2 IC9.3
RI_E: SV1.10 U$3.17
RI_S: U$3.1 X4.9
RS485A: A_L.1 A_R.1 IC9.6 SJ9.1 XL.3 XR.3
RS485B: B_L.1 B_R.1 IC9.7 SJ8.1 XL.6 XR.6
RST: IC5.29 JP3A.5 JP3B.5 R20.1
RST1: IC32.29 ISP2.5 R89.1
RTS_E: SV1.4 U$3.11
RTS_S: U$3.19 X4.7
RX: JP4.5 R35.2
RX_E: SV1.5 U$3.12
RX_S: U$3.20 X4.2
RXD: IC1.30 IC2.1
RXD2: IC13.1 IC15.30
RXD3: IC14.5 OK7.6
RXD4: IC20.1 OK5.3
RXD_AL1: IC19.5 OK5.6
SCK: IC1.17 ISP.3
SCK1: IC5.17 JP3A.3 JP3B.3 PB5.1
SCK2: IC15.17 ISP1.3
SCK3: IC32.17 ISP2.3
SCL: IC12.15 JP3.8
SDA: IC12.16 JP3.7
SPARE_B1: IC5.13 JP2.3 PB1.1 SW1.2
SPARE_C3: IC5.26 JP2.6 PC3.1 SW1.3
SPARE_C4: JP2.5 PC4.1 R21.1 R28.1
SPARE_C5: JP2.4 PC5.1 R23.1 R29.1
SPEC_RX: IC28.31 SPEKTRUM_TX.2
T_B: IC23.2 JP1T2.4 R19.1
T_G: IC24.2 JP1T2.3 R22.1
T_R: IC21.2 JP1T2.2 R24.1
T_U: IC25.2 JP1T2.6 R79.1
T_W: IC22.2 JP1T2.5 R18.1
TX: JP4.4 R36.2
TX_E: SV1.3 U$3.13
TX_S: U$3.21 X4.3
TXD: IC1.31 IC2.4
TXD2: D7.1 IC5.31 IC9.4
TXD3: IC13.4 IC15.31
TXD4: IC14.1 R48.2
TXD5: IC20.4 OK4.6
TXD_AL1: IC19.1 OK4.3
V+: B1.A G1.A JP1T.7 P+18T.1 R_R.2 U1.P$2 U1A.A W1.A@2 W1A.A
V+1: B6.A G6.A JP1T1.7 P+18T1.1 R_R1.2 U1A1.A U6.P$2 W1A1.A W7.A@2
VBUS: C84.2 U$2.3 U$3.7 U$3.8 X3.1
VCC: C33.1 C34.1 IC5.4 IC5.6 IC9.8 IC10.1 JP2.2 L3.1 PAD3.1 PAD4.1 R20.2 R21.2 R23.2 R25.1
VCC1: C82.2 C83.2 R83.1 SV1.1 U$3.5 U$3.6
VCC2: C103.2 IC34.8 LED+.1 R96.1 VCC1.1
XTAL1: C5.2 IC1.7 Q1.3
XTAL2: C4.2 IC1.8 Q1.1
XTAL3: C45.2 IC15.7 Q6.3
XTAL4: C46.2 IC15.8 Q6.1

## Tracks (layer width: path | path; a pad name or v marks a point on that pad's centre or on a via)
1.8V  (via drill 0.5)
  Top 0.406: v145.18,17.09 145.18,25.11 148.28,28.2 167.64,28.2 169.15,26.69 169.15,22.64 v169.55,22.25
  Bottom 0.406: C92.+ 171.52,25.24 C93.1 170.66,22.64 170.26,22.25 | SPEKTRUM_TX.4 148.83,13.44 v145.18,17.09 | 170.26,22.25 v169.55,22.25 168.99,21.69 IC29.1 169.03,20.75 R87.2 | 170.26,22.25
1_4
  Top 0.254: JP4.7 97.02,33.81 96.51,33.3 96.01,33.3 95.11,32.4 95.11,30.3 94.91,30.1 94.91,28.7 93.71,27.5 93.61,27.5 93.06,26.95 IC12.40
1_5
  Top 0.254: JP4.6 94.48,33.01 94.11,32.64 93.55,32.64 92.41,31.5 91.51,31.5 90.56,30.55 IC12.45
2_6
  Top 0.254: JP4.2 84.42,35.55 84.42,32.69 86.11,31 86.11,27.8 87.51,26.4 IC12.1
3.3V  (via drill 0.4)
  Top 0.254: 130.05,43.96 IC26.4 | 130.05,43.96 130.05,42.36 IC26.6 136.99,42.36 v136.99,42.45 | R80.1 137.74,49.91 v138.46,49.91 | 130.05,43.96 129.97,44.04 129.57,44.04 128.96,44.65 C76.1 | v131.24,36.98 131.7,36.98 LED4.A LED3.A
  Bottom 0.254: v138.46,49.91 136.99,48.37 136.99,45.63
  Bottom 0.406: 136.87,41.58 C80.1 137.8,40.97 138.38,40.39 138.38,37.85 137.51,36.98 v131.24,36.98 | 136.87,41.58 IC27.2 | 136.99,42.93 v136.99,42.45 136.99,41.18 136.87,41.58 | IC27.1 134.16,42.93 136.99,42.93 | 136.99,42.93 136.99,45.63 136.99,45.91 C81.+ 135.29,45 Q17.2
3.3V1  (via drill 0.4, 0.5)
  Top 0.254: 158.59,14.31 IC28.4 | 158.59,14.31 160.19,14.31 IC28.6 160.19,21.26 v159.07,21.26 | R84.1 152.64,22 v152.64,22.72 | 158.59,14.31 158.52,14.23 158.52,13.83 157.91,13.23 C85.1 | v165.58,15.5 165.58,15.96 BIND.A FRAME.A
